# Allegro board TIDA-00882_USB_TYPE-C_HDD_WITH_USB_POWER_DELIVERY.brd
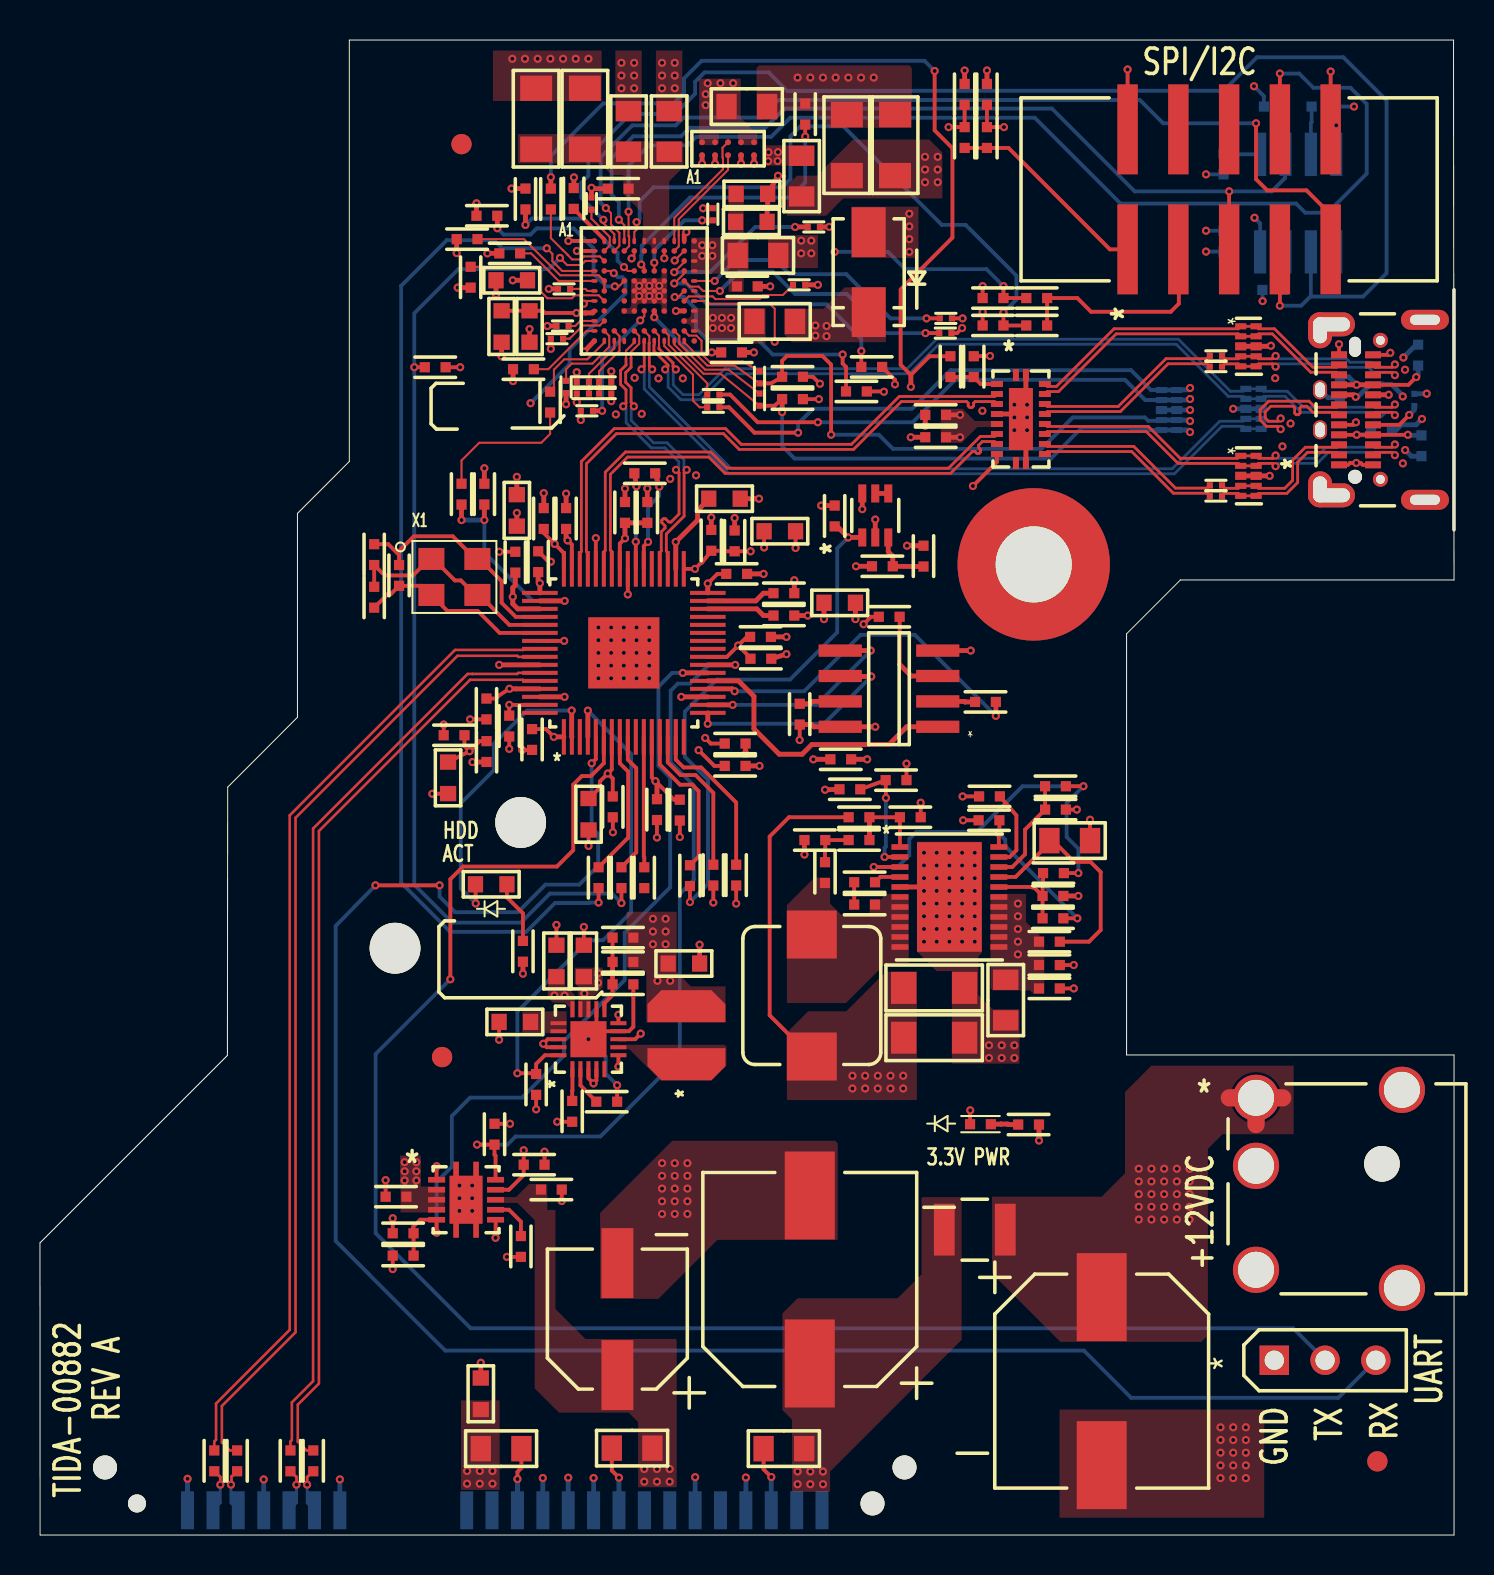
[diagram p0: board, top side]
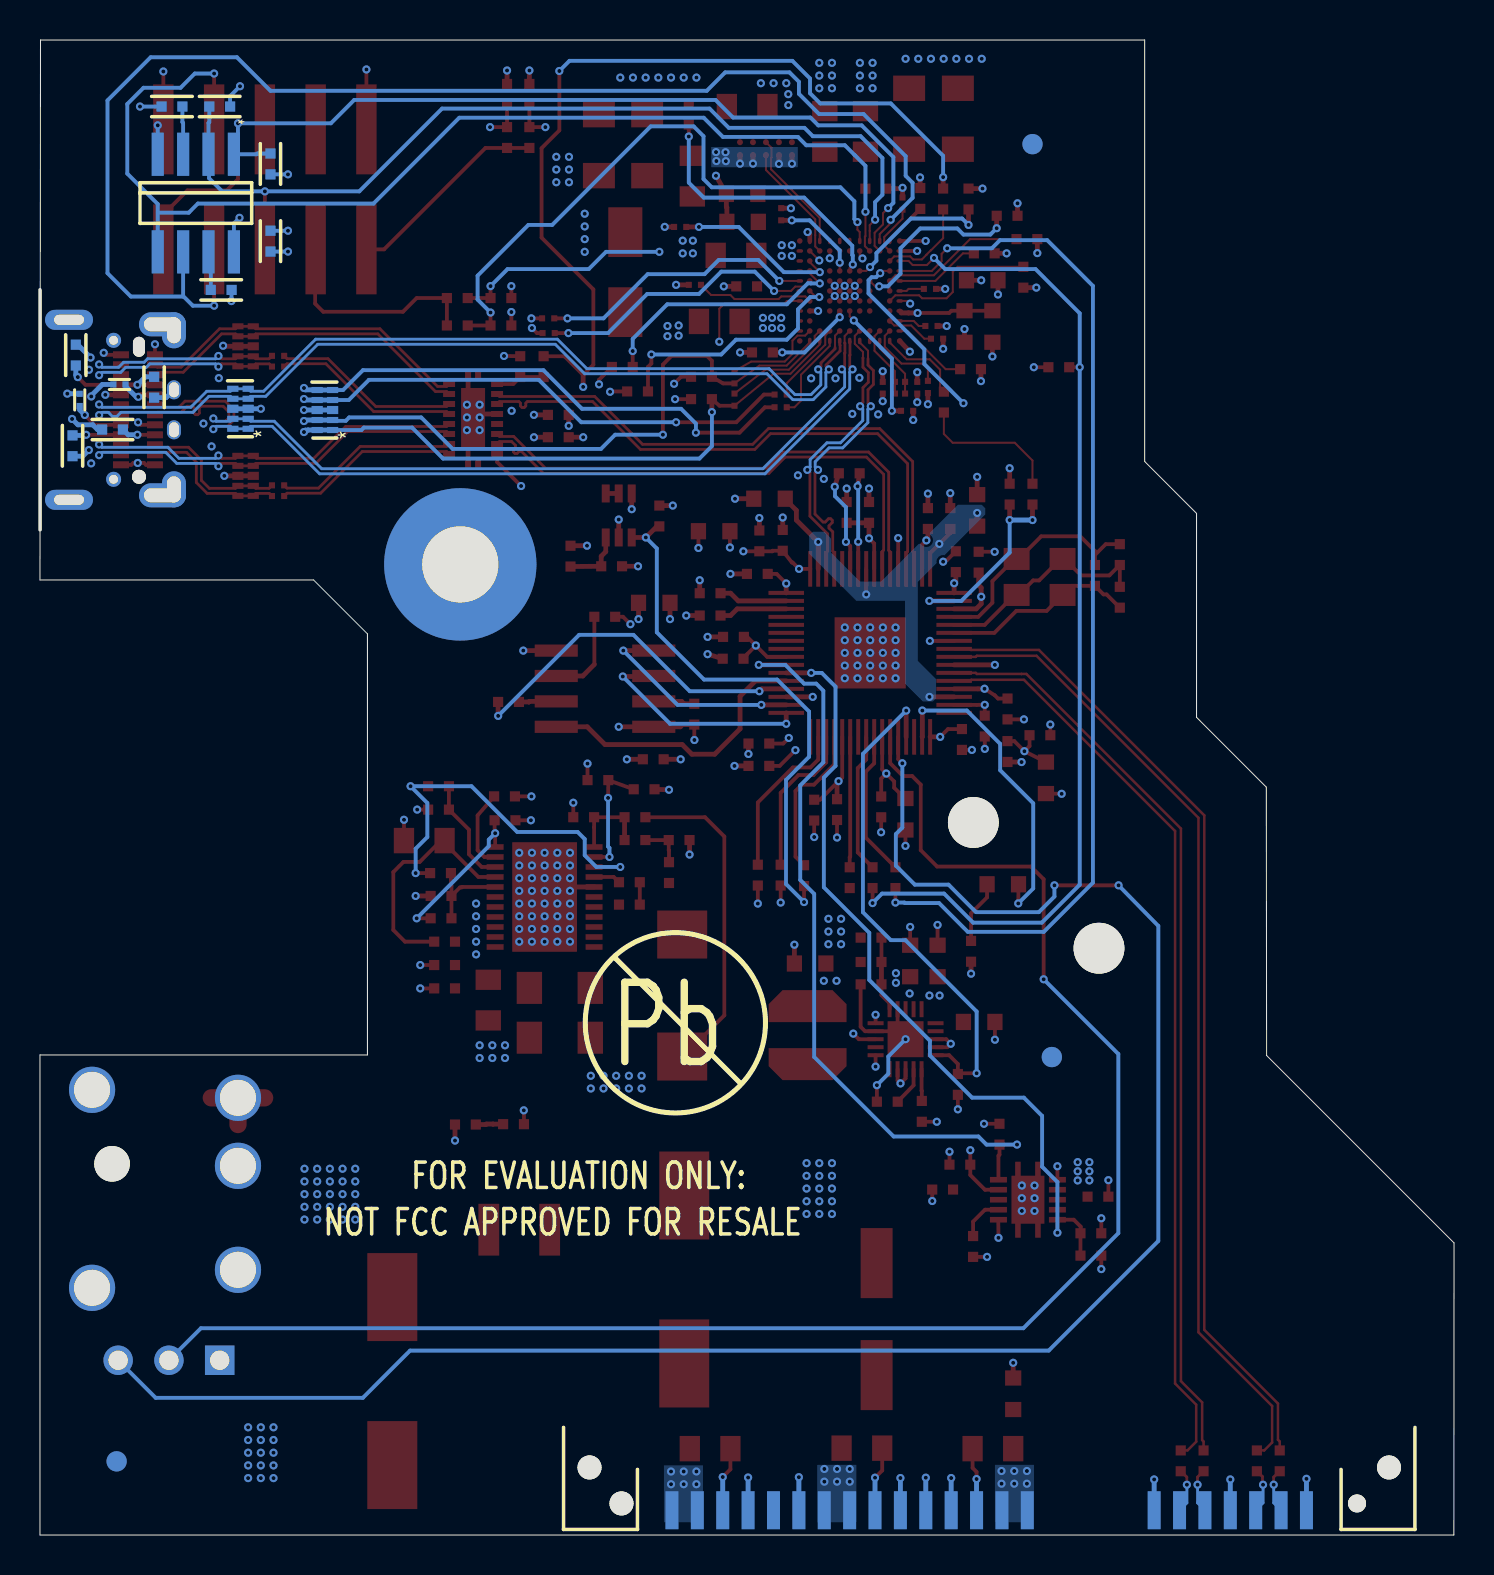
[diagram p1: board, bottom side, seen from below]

Outline 70.75 x 74.75 mm; copper layers: TOP, L2_GND, L3_SIG, L4_PWR, L5_GND, BOTTOM. Coordinates in mm from the lower left corner of the outline.
Outline path: 0,14.61 9.38,23.98 9.39,37.4 12.88,40.88 12.88,51.08 15.48,53.68 15.48,74.75 70.72,74.75 70.75,47.75 57.06,47.75 54.36,45.06 54.36,24 70.75,24 70.75,0 0.01,0 0,14.61

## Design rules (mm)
net group DIFFPAIR0: nets CRX2N CRX2P
net group DIFFPAIR1: nets CTX2N CTX2P
net group DIFFPAIR2: nets CTX1N CTX1P
net group DIFFPAIR3: nets CRX1N CRX1P
net group DIFFPAIR4: nets C_USB_BN C_USB_BP
net group DIFFPAIR5: nets C_USB_TN C_USB_TP
net group DIFFPAIR6: nets CTX2N_C CTX2P_C
net group DIFFPAIR7: nets CTX1N_C CTX1P_C
net group DIFFPAIR8: nets USB3_TX0N USB3_TX0P
net group DIFFPAIR9: nets USB3_RX0N USB3_RX0P
net group DIFFPAIR10: nets SATATXM SATATXP
net group DIFFPAIR11: nets SATARXM SATARXP
net group DIFFPAIR12: nets USB_RP_N USB_RP_P
net group DIFFPAIR13: nets CAP_SATATXM CAP_SATATXP
net group DIFFPAIR14: nets CAP_SATARXM CAP_SATARXP

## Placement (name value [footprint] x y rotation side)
C1  0.01uF  [0402]  68.95 59 270 bottom
C2  0.01uF  [0402]  65.04 57.39 90 bottom
C3  0.01uF  [0402]  69.12 54.46 90 bottom
C4  0.1 uF  [0402]  44.81 54.89 0 top
C5  0.01uF  [0402]  67.12 55.27 180 bottom
C6  0.01 uF  [0402]  44.81 56.01 0 top
C7  0.1uF  [0201]  58.83 58.96 0 top
C8  0.1uF  [0201]  58.83 58.42 0 top
C9  0.1uF  [0201]  58.83 52.48 0 top
C10  0.1uF  [0201]  58.83 51.95 0 top
C11  0.01uF  [0402]  8.72 3.71 90 top
C12  0.01uF  [0402]  12.53 3.71 90 top
C13  0.01uF  [0402]  13.67 3.71 90 top
C14  0.01uF  [0402]  9.86 3.71 90 top
C15  22uF  [0603]  22.06 7.06 90 top
C16  220uF  [CAP_RAD_SM_6P3X5P8MM]  28.89 10.79 180 top
C17  220uF  [CAP_RAD_SM_10X8MM]  38.51 12.78 180 top
C18  0.1uF  [0402]  40.06 38.79 0 top
C19  18pF  [0402]  16.72 46.89 90 top
C20  18pF  [0402]  16.72 49.02 270 top
C21  10uF  [0603]  27.45 36.04 270 top
C22  1uF  [0402]  36.07 43.81 0 top
C23  0.1uF  [0402]  36.05 44.91 0 top
C24  0.1uF  [0402]  28.66 36.41 270 top
C25  0.1uF  [0402]  23.78 48.64 90 top
C26  0.1uF  [0402]  25.2 50.83 90 top
C27  22uF  [0603]  34.25 51.82 0 top
C28  22uF  [0603]  20.42 37.86 270 top
C29  1uF  [0402]  22.34 39.17 270 top
C30  0.1uF  [0402]  23.48 40.45 270 top
C31  0.1uF  [0402]  22.34 41.3 270 top
C32  0.1uF  [0402]  30.87 36.27 270 top
C33  0.01uF  [0402]  24.93 48.67 90 top
C34  0.1uF  [0402]  24.62 39.78 270 top
C35  0.1uF  [0402]  34.78 38.46 0 top
C36  0.1uF  [0402]  32.01 36.25 270 top
C37  0.01uF  [0402]  34.78 39.57 0 top
C38  0.1uF  [0402]  20.72 39.99 180 top
C39  0.1uF  [0402]  34.86 48.06 0 top
C40  1uF  [0402]  26.32 50.83 90 top
C41  0.1uF  [0402]  29.27 51.13 90 top
C42  0.1uF  [0402]  33.59 49.73 90 top
C43  0.1uF  [0402]  34.76 49.71 90 top
C44  0.01uF  [0402]  30.39 51.13 90 top
C45  10uF  [0805]  35.36 71.42 180 top
C46  NC, 22uF  [1206]  40.37 69.49 270 top
C47  NC, 22uF  [1206]  42.78 69.49 270 top
C48  22uF  [1206]  24.82 70.82 270 top
C49  22uF  [1206]  27.26 70.82 270 top
C50  0.1uF  [0402]  28.93 67.32 0 top
C51  0.22uF  [0402]  34.6 59.13 180 top
C52  22uF  [0603]  35.62 67.06 180 top
C53  22uF  [0603]  35.59 65.66 180 top
C54  0.1uF  [0402]  35.39 62.43 180 top
C55  10uF  [0603]  24.49 60.43 90 top
C56  220pF  [0402]  37.65 57.91 180 top
C57  220pF  [0402]  37.65 56.79 180 top
C58  2.2uF  [0402]  26.7 66.83 270 top
C59  10uF  [0603]  23.6 62.74 0 top
C60  2.2uF  [0402]  23.5 64.08 0 top
C61  2.2uF  [0402]  24.19 58.29 0 top
C62  0.01uF  [0402]  59.22 64.69 270 bottom
C63  0.1uF  [0402]  50.5 27.33 0 top
C64  0.1uF  [0402]  50.5 28.5 0 top
C65  10uF  [0805]  48.32 26.75 270 top
C66  0.1uF  [0402]  41.26 31.52 180 top
C67  100uF  [1206]  44.74 27.36 0 top
C68  100uF  [1206]  44.74 24.87 0 top
C69  0.1uF  [0402]  38.77 34.75 180 top
C70  1000pF  [0402]  40.98 34.75 180 top
C71  220uF  [CAP_RAD_SM_10X8MM]  53.12 7.7 0 top
C72  1uF  [0402]  50.68 31.95 0 top
C73  0.1uF  [0402]  17.81 16.92 180 top
C74  22uF  [0603]  32.22 28.57 0 top
C75  30pF  [0402]  29.17 28.65 0 top
C76  22uF  [0603]  25.84 28.7 90 top
C77  22uF  [0603]  27.21 28.7 90 top
C78  0.1uF  [0402]  24.72 18.52 0 top
C79  0.1uF  [0402]  25.59 17.27 0 top
C80  0.1uF  [0402]  28.35 21.67 0 top
C81  22uF  [0603]  23.76 25.65 180 top
C82  4.7uF  [0805]  51.52 34.72 0 top
CN1  10029364-001LF  [CON_SMRT_10029364-001LF]  23.25 3.38 180 bottom
D1  LED White 0603  [0603]  22.58 32.54 0 top
D2  B340A-13-F  [SMA]  41.46 63.14 90 top
D3  LED Green 0402  [LED_0402]  47.05 20.54 180 top
F1  PTC FUSE  [FUSE_SM_135X110X43]  46.77 15.27 0 top
FB1  220 @ 100MHz  [0603]  40.01 46.61 180 top
FB2  220 @ 100MHz  [0603]  23.86 51.23 270 top
FB3  220 @ 100MHz  [0603]  37.02 50.19 180 top
FB4  NC, 21 @ 100MHZ  [0805]  29.45 70.18 90 top
FB5  21 @ 100MHZ  [0805]  31.48 70.18 90 top
FB6  21 @ 100MHZ  [0805]  35.92 63.98 180 top
FB7  21 @ 100MHZ  [0805]  36.76 60.68 0 top
FB8  220 @ 100MHz  [0603]  23.1 60.43 90 top
J1  TypeC_Receptacle_DualSMT_TOP  [USB_TYPEC_UT1211]  65.79 56.26 90 top
J2  NOPOP  [HDR_THVT_1X3_100]  61.76 8.74 90 top
J3  Header 5x2 0.1" Shroud SMT  [HDR_SMVT_SHRD_2X5_100]  59.49 67.28 90 top
J4  2.1mm x 5.5mm  [JACK_THRT_PJ-051AH]  60.84 21.86 0 top
L1  3.3uH  [IND_SM_SRP7030F]  38.62 26.97 270 top
L2  2.2uH  [IND_SM_VLCF4020]  32.34 24.99 90 top
MH1  Mounting Hole  [MFG_150_PTH]  49.72 48.53 0 top
NOREF  -  []  0.01 0 0 top
NOREF#2  -  []  15.76 11.93 90 top
NOREF#3  -  []  70.75 47.75 90 top
NOREF#4  -  []  54.36 24 0 top
NOREF#5  -  [unnamed#2]  21.09 69.55 0 top
NOREF#6  -  [unnamed#2]  24.05 35.63 0 top
NOREF#7  -  []  -3.8 -69.85 0 top
NOREF#8  -  [unnamed#2]  17.76 29.34 0 top
NOREF#9  -  [unnamed#2]  66.91 3.68 0 top
NOREF#10  -  []  0.01 0 0 top
NOREF#11  -  []  70.75 24 90 top
NOREF#12  -  []  70.75 0 90 top
NOREF#13  -  [unnamed#2]  20.12 23.9 0 top
NOREF#14  -  []  70.75 0 90 top
NOREF#15  -  []  15.48 74.75 0 top
NOREF#16  -  []  88.91 38.1 0 top
NOREF#17  -  [unnamed#2]  66.91 3.68 180 bottom
NOREF#18  -  [unnamed#2]  21.09 69.55 180 bottom
NOREF#19  -  [unnamed#2]  20.12 23.9 180 bottom
NOREF#20  -  []  12.39 18.28 180 bottom
NOREF#21  -  []  38.96 25.61 180 bottom
R1  2M  [0201]  68.76 56.76 270 bottom
R2  2M  [0201]  66.77 57.53 180 bottom
R3  0  [0402]  45.55 58.42 270 top
R4  NC, 0  [0402]  46.72 58.42 270 top
R5  10  [0805]  29.62 4.34 180 top
R6  4.7K  [0402]  38.01 41.04 270 top
R7  10  [0805]  23.07 4.32 0 top
R8  4.7K  [0402]  42.49 45.91 180 top
R9  10K  [0402]  30.26 53.09 180 top
R10  10  [0805]  37.22 4.32 180 top
R11  0  [0402]  47.31 41.65 180 top
R12  2M  [0402]  17.97 47.98 90 top
R13  56.2K  [0402]  21.09 52.04 90 top
R14  4.7K  [0402]  37.22 45.97 0 top
R15  4.7K  [0402]  37.22 47.09 0 top
R16  10K  [0402]  22.23 52.04 270 top
R17  330  [0402]  24.16 29.18 90 top
R18  NC, 0  [0402]  30.23 32.87 90 top
R19  0  [0402]  32.52 32.97 90 top
R20  NC, 0  [0402]  33.69 32.99 90 top
R21  0  [0402]  27.95 32.87 90 top
R22  0  [0402]  34.83 32.99 90 top
R23  0  [0402]  29.09 32.87 90 top
R24  NC, 0.005, 1%, 0.25W  [0805]  38.11 67.94 270 top
R25  0  [0402]  25.56 66.8 270 top
R26  0  [0402]  41.61 58.4 180 top
R27  0  [0402]  39.76 50.95 90 top
R28  0  [0201]  36 56.77 90 top
R29  0  [0201]  36 57.89 90 top
R30  NC, 0  [0201]  33.69 56.39 180 top
R31  NC, 0  [0201]  33.69 57.02 180 top
R32  15K  [0402]  21.55 62.89 270 top
R33  1M  [0201]  26.14 60.45 180 top
R34  1M  [0201]  25.87 59.82 180 top
R35  1K  [0402]  24.29 66.8 270 top
R36  1K  [0402]  22.36 65.96 0 top
R37  1M  [0201]  45.32 60.83 0 top
R38  3.3K  [0402]  59.22 68.55 90 bottom
R39  100K  [0402]  40.85 57.18 180 top
R40  3.3K  [0402]  61.76 71.42 0 bottom
R41  3.3K  [0402]  61.68 62.26 0 bottom
R42  3.3K  [0402]  64.14 71.42 0 bottom
R43  3.3K  [0402]  47.38 72.03 270 top
R44  3.3K  [0402]  47.68 61.85 0 top
R45  3.3K  [0402]  46.26 72.03 270 top
R46  3.3K  [0402]  47.68 60.48 0 top
R47  0  [0402]  46.26 69.88 90 top
R48  0  [0402]  49.87 60.48 180 top
R49  NC, 0  [0402]  49.87 61.85 180 top
R50  NC, 0  [0402]  47.38 69.88 90 top
R51  100K  [0402]  21.37 64.8 180 top
R52  100K  [0402]  38.29 71.04 90 top
R54  1M  [0201]  26.32 57.4 270 top
R55  1M  [0201]  27.59 66.57 90 top
R56  NC, 1K  [0201]  27.16 57.66 180 top
R57  NC, 1K  [0201]  28.28 57.66 0 top
R58  1M  [0201]  38.72 65.41 0 top
R59  1M  [0201]  45.3 60.1 0 top
R60  1M  [0201]  37.98 62.51 0 top
R61  1M  [0201]  33.66 66.04 90 top
R62  1M  [0201]  27.16 57.07 180 top
R63  1M  [0201]  28.28 57.07 0 top
R64  NC, 0  [0201]  26.22 62.31 0 top
R65  1M  [0201]  27.36 56.21 180 top
R66  750K  [0402]  44.2 48.95 90 top
R67  470K  [0402]  42.83 37.74 0 top
R68  2K  [0402]  39.28 33.12 90 top
R69  76.8K  [0402]  40.98 35.89 0 top
R70  3.01  [0402]  41.26 32.64 180 top
R71  120K  [0402]  42.15 48.44 0 top
R72  200K  [0402]  40.52 37.29 0 top
R73  NC, TBD  [0402]  50.68 30.84 0 top
R74  NC, TBD  [0402]  50.81 37.44 0 top
R75  100K  [0402]  47.51 36.93 0 top
R76  10K  [0402]  43.54 35.89 0 top
R77  NC, TBD  [0402]  47.48 35.74 0 top
R78  100K  [0402]  50.81 36.27 180 top
R79  100K  [0402]  50.71 33.1 180 top
R80  400K  [0402]  29.17 29.87 180 top
R81  10K  [0402]  22.74 20.04 270 top
R82  475K  [0402]  29.17 27.53 180 top
R83  4.7K  [0402]  18.17 15.09 180 top
R84  4.7K  [0402]  26.63 21.18 90 top
R85  4.7K  [0402]  24.82 22.53 270 top
R86  NC, 4.7K  [0402]  18.17 13.97 180 top
R87  20K  [0402]  24.06 14.43 270 top
R88  330  [0402]  49.46 20.52 0 top
R89  0  [0402]  50.5 29.67 180 top
R90  0  [0402]  25.52 56.65 90 top
R91  10K  [0402]  19.77 58.39 180 top
U1  HD3SS3212  [RKS_R-PVQFN-N20]  49.08 55.8 0 top
U2  TPD4E05U06  [DQA]  60.46 52.96 270 top
U3  TPD4E05U06  [DQA]  60.46 59.44 270 top
U4  TPD4E05U06  [DQA]  56.49 56.25 90 bottom
U5  TPD4E05U06  [DQA]  60.71 56.31 90 bottom
U6  TUSB9261PVP  [PVP_QFP_64]  29.21 44.11 90 top
U7  M25P10-AVMN6TP  [SOIC_8_197X157_50]  42.48 42.32 180 top
U8  NC, CSD87501L  [YJG0010AA]  34.42 69.32 90 top
U9  TPS65982  [ZQZ_BGA_96]  30.23 62.2 0 top
U10  W25Q80DVSNIG  [SOIC_8_197X157_50]  62.95 66.6 270 bottom
U11  TPS53318  [DQP_PSON_22]  45.5 31.9 0 top
U12  TLV3012AIDCK  [DCK_PDSO_6]  41.79 50.98 90 top
U13  TPS650061  [RUK_S_PWQFN-N20]  27.44 24.79 90 top
U14  TPS2561DRC  [DRC_S_PVSON_N10]  21.32 16.76 0 top
X1  40MHz  [ECX-32]  20.73 47.9 0 top

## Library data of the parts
C1-C6 C45-C62 = cc0402
C7-C15 C18-C44 C63-C70 C72-C82 = CAP NP
C16 C17 C71 = CAP POL
CN1 = 0876781001
D1 = DIODE_4
D2 = DIODE SCHOTTKY_1
D3 = DIODE_5
F1 = FUSE
FB1-FB8 = FERRITE BEAD
J1 = USBTypeC_Receptacle_TOPMount_0
J2 = HDR3X1 M .1
J3 = CONN PCB 5x2-S
J4 = BNC_0
L1 = INDUCTOR
L2 = INDUCTOR FERRITE
MH1 = Mounting Hole
R1 R2 R25-R52 R54 R55 R58-R63 R65 R90 R91 = R_2
R3-R23 R56 R57 R64 R66-R89 = R
R24 = RESISTOR
U1 = HD3SS3212_0
U2-U5 = TPD4E05U06
U6 = TUSB9260PAP_0
U7 = Pm25LV512A
U8 = CDS87501L
U9 = TPS65982
U10 = W25Q80SSI
U11 = TPS53318
U12 = TLV3012
U13 = TPS650061_0
U14 = TPS2560DRC_1
X1 = X OR Y_0

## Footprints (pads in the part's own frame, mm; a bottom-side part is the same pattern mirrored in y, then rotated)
0201
  rect 0.305x0.305 smd: 1(-0.305,0) 2(0.305,0)
0402
  rect 0.508x0.508 smd: 1(-0.521,0) 2(0.521,0)
0603
  rect 0.762x0.813 smd: 1(-0.787,0) 2(0.787,0)
0805
  rect 1.016x1.27 smd: 1(-1.016,0) 2(1.016,0)
1206
  rect 1.27x1.6 smd: 1(-1.524,0) 2(1.524,0)
CAP_RAD_SM_6P3X5P8MM
  rect 1.6x3.5 smd: 1(0,2.8) 2(0,-2.8)
CAP_RAD_SM_10X8MM
  rect 2.5x4.4 smd: 1(0,4.2) 2(0,-4.2)
CON_SMRT_10029364-001LF
  round 1.2 hole 1.2 unplated: (-20,0) (-18.4,-1.8) (20,0)
  round 0.9 hole 0.9 unplated: (18.4,-1.8)
  rect 0.65x1.9 smd: P1(1.905,-2.14) P2(0.635,-2.14) P3(-0.635,-2.14) P4(-1.905,-2.14) P5(-3.175,-2.14) P6(-4.445,-2.14) P7(-5.715,-2.14) P8(-6.985,-2.14) P9(-8.255,-2.14) P10(-9.525,-2.14) P11(-10.795,-2.14) P12(-12.065,-2.14) P13(-13.335,-2.14) P14(-14.605,-2.14) P15(-15.875,-2.14) S1(15.87,-2.14) S2(14.6,-2.14) S3(13.33,-2.14) S4(12.06,-2.14) S5(10.79,-2.14) S6(9.52,-2.14) S7(8.25,-2.14)
DCK_PDSO_6
  rect 0.9x0.4 smd: 1(-1.1,0.65) 2(-1.1,0) 3(-1.1,-0.65) 4(1.1,-0.65) 5(1.1,0) 6(1.1,0.65)
DQA
  rect 0.305x0.559 smd: 1(-1,-0.385) 2(-0.5,-0.385) 4(0.5,-0.385) 5(1,-0.385) 6(1,0.385) 7(0.5,0.385) 9(-0.5,0.385) 10(-1,0.385)
  rect 0.406x0.559 smd: 3(0,-0.385) 8(0,0.385)
DQP_PSON_22
  rect 0.85x0.28 smd: 1(-2.475,2.5) 2(-2.475,2) 3(-2.475,1.5) 4(-2.475,1) 5(-2.475,0.5) 6(-2.475,0) 7(-2.475,-0.5) 8(-2.475,-1) 9(-2.475,-1.5) 10(-2.475,-2) 11(-2.475,-2.5) 12(2.475,-2.5) 13(2.475,-2) 14(2.475,-1.5) 15(2.475,-1) 16(2.475,-0.5) 17(2.475,0) 18(2.475,0.5) 19(2.475,1) 20(2.475,1.5) 21(2.475,2) 22(2.475,2.5)
  rect 3.24x5.48 smd: 23(0,0)
DRC_S_PVSON_N10
  rect 0.85x0.28 smd: 1(-1.475,1) 2(-1.475,0.5) 3(-1.475,0) 4(-1.475,-0.5) 5(-1.475,-1) 6(1.475,-1) 7(1.475,-0.5) 8(1.475,0) 9(1.475,0.5) 10(1.475,1)
  custom 0.412x0.412 smd: 11(0,0)
ECX-32
  rect 1.3x1.1 smd: 1(-1.15,-0.9) 2(1.15,-0.9) 3(1.15,0.9) 4(-1.15,0.9)
FUSE_SM_135X110X43
  rect 1.041x2.591 smd: 1(-1.524,0) 2(1.524,0)
HDR_SMVT_SHRD_2X5_100
  rect 4.5x1.02 smd: 1(-3,5.08) 2(3,5.08) 3(-3,2.54) 4(3,2.54) 5(-3,0) 6(3,0) 7(-3,-2.54) 8(3,-2.54) 9(-3,-5.08) 10(3,-5.08)
HDR_THVT_1X3_100
  rect 1.473x1.473 hole 0.965: 1(0,0)
  round 1.473 hole 0.965: 2(0,-2.54) 3(0,-5.08)
IND_SM_SRP7030F
  rect 2.4x2.5 smd: 1(-3.05,0) 2(3.05,0)
IND_SM_VLCF4020
  custom 0.4x0.4 smd: 1(-1.45,0) 2(1.45,0)
JACK_THRT_PJ-051AH
  round 1.778 hole 1.778 unplated: (6.3,-3.3)
  round 2.311 hole 1.803: 1(0,0) 2(0,-8.6) 3(0,-3.4) 4(7.3,-9.5) 5(7.3,0.4)
LED_0402
  rect 0.508x0.508 smd: 1(-0.521,0) 2(0.521,0)
MFG_150_PTH
  round 7.62 hole 3.81: 1(0,0)
PVP_QFP_64
  rect 1.78x0.2 smd: 1(-4.2,3) 2(-4.2,2.6) 3(-4.2,2.2) 4(-4.2,1.8) 5(-4.2,1.4) 6(-4.2,1) 7(-4.2,0.6) 8(-4.2,0.2) 9(-4.2,-0.2) 10(-4.2,-0.6) 11(-4.2,-1) 12(-4.2,-1.4) 13(-4.2,-1.8) 14(-4.2,-2.2) 15(-4.2,-2.6) 16(-4.2,-3) 33(4.2,-3) 34(4.2,-2.6) 35(4.2,-2.2) 36(4.2,-1.8) 37(4.2,-1.4) 38(4.2,-1) 39(4.2,-0.6) 40(4.2,-0.2) 41(4.2,0.2) 42(4.2,0.6) 43(4.2,1) 44(4.2,1.4) 45(4.2,1.8) 46(4.2,2.2) 47(4.2,2.6) 48(4.2,3)
  rect 0.2x1.78 smd: 17(-3,-4.2) 18(-2.6,-4.2) 19(-2.2,-4.2) 20(-1.8,-4.2) 21(-1.4,-4.2) 22(-1,-4.2) 23(-0.6,-4.2) 24(-0.2,-4.2) 25(0.2,-4.2) 26(0.6,-4.2) 27(1,-4.2) 28(1.4,-4.2) 29(1.8,-4.2) 30(2.2,-4.2) 31(2.6,-4.2) 32(3,-4.2) 49(3,4.2) 50(2.6,4.2) 51(2.2,4.2) 52(1.8,4.2) 53(1.4,4.2) 54(1,4.2) 55(0.6,4.2) 56(0.2,4.2) 57(-0.2,4.2) 58(-0.6,4.2) 59(-1,4.2) 60(-1.4,4.2) 61(-1.8,4.2) 62(-2.2,4.2) 63(-2.6,4.2) 64(-3,4.2)
  rect 3.56x3.56 smd: 65(0,0)
RKS_R-PVQFN-N20
  rect 0.3x0.6 smd: 1(-0.25,2.2) 10(-0.25,-2.2) 11(0.25,-2.2) 20(0.25,2.2)
  rect 0.6x0.3 smd: 2(-1.2,1.75) 3(-1.2,1.25) 4(-1.2,0.75) 5(-1.2,0.25) 6(-1.2,-0.25) 7(-1.2,-0.75) 8(-1.2,-1.25) 9(-1.2,-1.75) 12(1.2,-1.75) 13(1.2,-1.25) 14(1.2,-0.75) 15(1.2,-0.25) 16(1.2,0.25) 17(1.2,0.75) 18(1.2,1.25) 19(1.2,1.75)
  rect 1.2x3.1 smd: 21(0,0)
RUK_S_PWQFN-N20
  rect 0.8x0.2 smd: 1(-1.5,0.8) 2(-1.5,0.4) 3(-1.5,0) 4(-1.5,-0.4) 5(-1.5,-0.8) 11(1.5,-0.8) 12(1.5,-0.4) 13(1.5,0) 14(1.5,0.4) 15(1.5,0.8)
  rect 0.2x0.8 smd: 6(-0.8,-1.5) 7(-0.4,-1.5) 8(0,-1.5) 9(0.4,-1.5) 10(0.8,-1.5) 16(0.8,1.5) 17(0.4,1.5) 18(0,1.5) 19(-0.4,1.5) 20(-0.8,1.5)
  rect 1.8x1.8 smd: 21(0,0)
SMA
  rect 2.489x1.702 smd: 1(-2,0) 2(2,0)
SOIC_8_197X157_50
  rect 2.159x0.61 smd: 1(-2.44,1.905) 2(-2.44,0.635) 3(-2.44,-0.635) 4(-2.44,-1.905) 5(2.44,-1.905) 6(2.44,-0.635) 7(2.44,0.635) 8(2.44,1.905)
unnamed#2
  round 1.016 smd: (0,0)
USB_TYPEC_UT1211
  round 0.7 hole 0.7 unplated: (-3.35,0)
  oval 1x0.6 hole 1x0.6 unplated: (3.15,0)
  round 0.75 hole 0.45: 1(-3.475,-1.27) 2(3.475,-1.27)
  oval 1x2.4 hole 0.5x1.5: 3(-4.5,-3.5) 4(4.5,-3.5)
  oval 0.95x0.7 hole 0.75x0.5: 5(-1,1.75) 6(1,1.75)
  oval 1.2x2.35 hole 0.7x1.85: 7(4.275,1.175) 8(-4.275,1.175)
  oval 1.8x1.2 hole 1.3x0.7: 9(-3.975,1.75) 10(3.975,1.75)
  rect 0.35x0.8 smd: A1(-2.75,0.8) A2(-2.25,0.8) A3(-1.75,0.8) A4(-1.25,0.8) A5(-0.75,0.8) A6(-0.25,0.8) A7(0.25,0.8) A8(0.75,0.8) A9(1.25,0.8) A10(1.75,0.8) A11(2.25,0.8) A12(2.75,0.8) B1(2.75,-0.9) B2(2.25,-0.9) B3(1.75,-0.9) B4(1.25,-0.9) B5(0.75,-0.9) B6(0.25,-0.9) B7(-0.25,-0.9) B8(-0.75,-0.9) B9(-1.25,-0.9) B10(-1.75,-0.9) B11(-2.25,-0.9) B12(-2.75,-0.9)
YJG0010AA
  round 0.3 smd: A1(-0.325,1.3) A2(0.325,1.3) B1(-0.325,0.65) B2(0.325,0.65) C1(-0.325,0) C2(0.325,0) D1(-0.325,-0.65) D2(0.325,-0.65) E1(-0.325,-1.3) E2(0.325,-1.3)
ZQZ_BGA_96
  round 0.28 smd: A1(-2.5,2.5) A11(2.5,2.5) B2(-2,2) B3(-1.5,2) B4(-1,2) B5(-0.5,2) B6(0,2) B7(0.5,2) B8(1,2) B9(1.5,2) B10(2,2) C2(-2,1.5) C10(2,1.5) D2(-2,1) D5(-0.5,1) D6(0,1) D7(0.5,1) D8(1,1) D10(2,1) E2(-2,0.5) E4(-1,0.5) E5(-0.5,0.5) E6(0,0.5) E7(0.5,0.5) E8(1,0.5) E10(2,0.5) F2(-2,0) F4(-1,0) F5(-0.5,0) F6(0,0) F7(0.5,0) F8(1,0) F10(2,0) G2(-2,-0.5) G4(-1,-0.5) G5(-0.5,-0.5) G6(0,-0.5) G7(0.5,-0.5) G8(1,-0.5) G10(2,-0.5) H2(-2,-1) H4(-1,-1) H5(-0.5,-1) H6(0,-1) H7(0.5,-1) H8(1,-1) H10(2,-1) J2(-2,-1.5) J10(2,-1.5) K2(-2,-2) K3(-1.5,-2) K4(-1,-2) K5(-0.5,-2) K6(0,-2) K7(0.5,-2) K8(1,-2) K9(1.5,-2) K10(2,-2) L1(-2.5,-2.5) L11(2.5,-2.5)
  oval 0.18x0.33 smd: A2(-2,2.5) A3(-1.5,2.5) A4(-1,2.5) A5(-0.5,2.5) A6(0,2.5) A7(0.5,2.5) A8(1,2.5) A9(1.5,2.5) A10(2,2.5) L2(-2,-2.5) L3(-1.5,-2.5) L4(-1,-2.5) L5(-0.5,-2.5) L6(0,-2.5) L7(0.5,-2.5) L8(1,-2.5) L9(1.5,-2.5) L10(2,-2.5)
  oval 0.33x0.18 smd: B1(-2.5,2) B11(2.5,2) C1(-2.5,1.5) C11(2.5,1.5) D1(-2.5,1) D11(2.5,1) E1(-2.5,0.5) E11(2.5,0.5) F1(-2.5,0) F11(2.5,0) G1(-2.5,-0.5) G11(2.5,-0.5) H1(-2.5,-1) H11(2.5,-1) J1(-2.5,-1.5) J11(2.5,-1.5) K1(-2.5,-2) K11(2.5,-2)

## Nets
GND: C1.1 C2.1 C3.1 C4.1 C5.1 C6.1 C15.2 C16.2 C17.2 C18.2 C21.2 C22.2 C23.2 C24.2 C25.2 C26.2 C27.2 C28.2 C29.2 C30.2 C31.2 C32.2 C33.2 C34.2 C35.2 C36.2 C37.2 C38.2 C39.2 C40.2 C41.2 C42.2 C43.2 C44.2 C45.1 C46.1 C47.1 C48.1 C49.1 C50.1 C51.1 C52.1 C53.1 C54.1 C55.1 C56.1 C57.1 C58.1 C59.1 C60.1 C61.1 C62.1 C63.2 C64.2 C65.2 C67.2 C68.2 C71.2 C72.2 C73.2 C74.2 C76.2 C77.2 C78.2 C79.2 C80.2 C81.2 C82.2 CN1.P4(GND#P4) CN1.P5(GND#P5) CN1.P6(GND#P6) CN1.P10(GND#P10) CN1.P12(GND#P12) CN1.S1(GND#S1) CN1.S4(GND#S4) CN1.S7(GND#S7) D2.2(ANODE) J1.1(SHIELD1) J1.2(SHIELD2) J1.3(SHIELD3) J1.4(SHIELD4) J1.5(SHIELD5) J1.6(SHIELD6) J1.7(SHIELD7) J1.8(SHIELD8) J1.9(SHIELD9) J1.10(SHIELD10) J1.A1(GND0) J1.A12(GND1) J1.B1(GND2) J1.B12(GND3) J2.1 J3.2(6) J3.10 J4.2(S) J4.3(SW) J4.4(GND#4) J4.5(GND#5) MH1.1(GND) R1.1 R2.1 R4.1 R16.1 R32.2 R33.2 R34.2 R37.2 R51.2 R52.2 R54.2 R55.2 R58.2 R59.2 R60.2 R61.2 R62.2 R63.2 R64.1 R65.2 R71.1 R72.1 R75.1 R76.2 R77.1 R78.1 R82.1 R86.2 R87.2 R88.2 U1.5(GND#5) U1.11(GND#11) U1.20(GND#20) U1.21(PPAD) U2.3(GND#3) U2.8(GND#8) U3.3(GND#3) U3.8(GND#8) U4.3(GND#3) U4.8(GND#8) U5.3(GND#3) U5.8(GND#8) U6.44(VSS#44) U6.58(VSS#58) U6.65(VSS#65) U7.4(GND) U9.A1(GND#A1) U9.B8(GND#B8) U9.D8(GND#D8) U9.E5(GND#E5) U9.E6(GND#E6) U9.E7(GND#E7) U9.E8(GND#E8) U9.F5(GND#F5) U9.F6(GND#F6) U9.F7(GND#F7) U9.F8(GND#F8) U9.G5(GND#G5) U9.G6(GND#G6) U9.G7(GND#G7) U9.G8(GND#G8) U9.H4(GND#H4) U9.H5(GND#H5) U9.H8(GND#H8) U9.L1(GND#L1) U10.4(GND) U11.5(ROVP) U11.23(GND) U12.2(V-) U13.6(PGND) U13.9(MODE) U13.12(AGND) U13.21(PWR_PAD) U14.1(GND) U14.11(PAD)
SV5: CN1.P7(V5#P7) R5.2
SV12: CN1.P13(V12#P13) R10.2
SV33: CN1.P3(V33#P3) R7.2
VDD_1P1V: C28.1 C29.1 C30.1 C31.1 C32.1 C33.1 C34.1 C35.1 C36.1 C37.1 C38.1 C39.1 C40.1 C41.1 C42.1 C43.1 C44.1 FB3.2 U6.1(VDD#1) U6.12(VDD#12) U6.19(VDD#19) U6.32(VDD#32) U6.33(VDD#33) U6.41(VDD#41) U6.47(VDD#47) U6.49(VDD#49) U6.55(VDD#55) U6.61(VDD#61) U6.63(VDD#63)
VDD_3P3V: C21.1 C22.1 C23.1 C24.1 C25.1 FB1.2 R14.2 R15.2 R81.1 R83.2 R85.2 U6.7(VDDSHV#7) U6.24(VDDSHV#24) U6.51(VDD33)
VDDA_3P3V: C26.1 C27.1 FB2.2 U6.34(VDDA33#34) U6.40(VDDA33#40) U6.48(VDDA33#48) U6.62(VDDA33#62)
VIN_3V3: C55.2 FB8.2 U9.B1(VDDIO) U9.H1(VIN_3V3)
VSSOSC: C19.2 C20.2 U6.53(VSSOSC) X1.2(GND#2) X1.4(GND#4)
3212OEN: R3.2 R4.2 U1.2(OEN)
53318_EN: R67.1 R72.2 U11.2(EN)
53318_LL: C66.1 L1.1 R68.1 U11.6(LL1) U11.7(LL2) U11.8(LL3) U11.9(LL4) U11.10(LL5) U11.11(LL6)
53318_MODE: R74.1 R78.2 U11.20(MODE)
65982_5V: C52.2 C53.2 C54.2 FB6.2 U9.A11(PP_5V0_2) U9.B11(PP_5V0_1) U9.C11(PP_5V0_3) U9.D11(PP_5V0_4) U9.H10(PP_CABLE)
65982_VBUS: C45.2 FB7.1 U8.A2(S2_1) U8.B2(S2_2) U8.D2(S2_3) U8.E2(S2_4) U9.H11(VBUS1) U9.J10(VBUS2) U9.J11(VBUS3) U9.K11(VBUS4)
87501_S1: R24.1 U8.A1(S1_1) U8.B1(S1_2) U8.D1(S1_3) U8.E1(S1_4) U9.A10(SENSEN)
AUX_N: R34.1 U9.J2(AUX_N)
AUX_P: R33.1 U9.J1(AUX_P)
BOARD_1P1V: C74.1 C75.2 FB3.1 L2.2 R80.1
BOARD_1P8V: C81.1 U13.16(FB_LDO2) U13.17(VLDO2)
BOARD_3P3V: C4.2 C6.2 C15.1 C18.1 C77.1 CN1.P1(V33#P1) CN1.P2(V33#P2) D3.2(A) FB1.1 FB2.1 FB8.1 R6.2 R7.1 R8.2 R17.1 U1.6(VCC) U7.8(VCC) U13.13(FB_LDO1) U13.14(VLDO1)
BOARD_5V: C67.1 C68.1 C69.2 C73.1 FB4.2 FB6.1 L1.2 R69.1 U14.2(IN#2) U14.3(IN#3) U14.4(EN1)
BOARD_12V: C46.2 C47.2 C63.1 C64.1 C65.1 C71.1 F1.2 FB5.2 J4.1(T) R24.2 R66.2 R67.2 R89.2 U9.B10(SENSEP) U11.12(VIN1) U11.13(VIN2) U11.14(VIN3) U11.15(VIN4) U11.16(VIN5) U11.17(VIN6)
C_CC1: C57.2 J1.A5(CC1) R28.1 U4.1(D1+) U4.10(NC10) U9.L9(C_CC1)
C_CC2: C56.2 J1.B5(CC2) R29.1 U4.2(D1-) U4.9(NC9) U9.L10(C_CC2)
C_USB_BN: J1.B7(DN2) U5.4(D2+) U5.7(NC7) U9.L7(C_USB_BN)
C_USB_BP: J1.B6(DP2) U5.5(D2-) U5.6(NC6) U9.K7(C_USB_BP)
C_USB_TN: J1.A7(DN1) U5.1(D1+) U5.10(NC10) U9.L6(C_USB_TN)
C_USB_TP: J1.A6(DP1) U5.2(D1-) U5.9(NC9) U9.K6(C_USB_TP)
CABLE_PLUG: R13.2 R90.1
CAP_SATARXM: C12.1 CN1.S5(B-)
CAP_SATARXP: C13.1 CN1.S6(B+)
CAP_SATATXM: C11.1 CN1.S2(A+)
CAP_SATATXP: C14.1 CN1.S3(A-)
CRX1N: J1.B10(SSRXN1) U1.15(C0P) U2.1(D1+) U2.10(NC10)
CRX1P: J1.B11(SSRXP1) U1.14(C0N) U2.2(D1-) U2.9(NC9)
CRX2N: J1.A10(SSRXN2) U1.18(B0N) U3.2(D1-) U3.9(NC9)
CRX2P: J1.A11(SSRXP2) U1.19(B0P) U3.1(D1+) U3.10(NC10)
CSBU1: J1.A8(SBU1) R2.2 R31.1 U4.4(D2+) U4.7(NC7)
CSBU1_TPS65982: R31.2 U9.K8(C_SBU1)
CSBU2: J1.B8(SBU2) R1.2 R30.1 U4.5(D2-) U4.6(NC6)
CSBU2_TPS65982: R30.2 U9.L8(C_SBU2)
CTX1N: C9.2 J1.A3(SSTXN1) U2.4(D2+) U2.7(NC7)
CTX1N_C: C9.1 U1.13(C1P)
CTX1P: C10.2 J1.A2(SSTXP1) U2.5(D2-) U2.6(NC6)
CTX1P_C: C10.1 U1.12(C1N)
CTX2N: C8.2 J1.B3(SSTXN2) U3.5(D2-) U3.6(NC6)
CTX2N_C: C8.1 U1.16(B1N)
CTX2P: C7.2 J1.B2(SSTXP2) U3.4(D2+) U3.7(NC7)
CTX2P_C: C7.1 U1.17(B1P)
DBG_CTL1: R36.2 U9.E4(DBG_CTL1)
DBG_CTL2: R35.2 U9.D5(DBG_CTL2)
DEBUG1: R90.2 U9.L2(DEBUG1)
DEBUG2: R54.1 U9.K2(DEBUG2)
DEBUG3: R56.1 R62.1 U9.L3(DEBUG3)
DEBUG4: R57.1 R63.1 U9.K3(DEBUG4)
FAULT#: R81.2 U6.23(SPI_CS2_GPIO11) U14.6(FAULT2Z) U14.10(FAULT1Z)
FB_DCDC: C75.1 R80.2 R82.2 U13.11(FB_DCDC)
FREQSEL0: R14.1 U6.30(FREQSEL0)
FREQSEL1: R15.1 U6.31(FREQSEL1)
FUSE_12V: C17.1 CN1.P14(V12#P14) CN1.P15(V12#P15) F1.1 R10.1
G1: R28.2 U9.K9(RPD_G1)
G2: R29.2 U9.K10(RPD_G2)
GPIO0: R55.1 U9.B2(GPIO0)
GPIO0_9261: R21.2 U6.8(GPIO0)
GPIO1: R25.2 U9.C2(GPIO1)
GPIO1_9261: R23.2 U6.9(GPIO1)
GPIO2: R26.2 U9.D10(GPIO2)
GPIO3: R27.2 U9.G11(GPIO3)
GPIO3_9261: R18.2 U6.11(GPIO3)
GPIO4: R58.1 U9.C10(GPIO4)
GPIO4_9261: R19.2 U6.13(GPIO4)
GPIO5: R59.1 U9.E10(GPIO5)
GPIO5_9261: R20.2 U6.14(GPIO5)
GPIO6: R60.1 U9.G10(GPIO6)
GPIO6_9261: R22.2 U6.15(GPIO6)
GPIO7: R61.1 U9.D7(GPIO7)
GPIO8: R65.1 U9.H6(GPIO8)
GRST#: R85.1 U6.4(GRSTZ) U13.20(RST#)
HDD_LED#: D1.1(K) U6.2(PWM0)
HLD#: R6.1 U7.7(HOLD#)
HRESET: R52.1 U9.D6(HRESET)
HV_GATE1: U8.C1(G1) U9.B9(HV_GATE1)
HV_GATE2: U8.C2(G2) U9.A9(HV_GATE2)
I2C_ADDR: R64.2 U9.F1(I2C_ADDR)
I2C_IRQ1Z: R23.1 R91.2 U9.C1(I2C_IRQ1Z)
I2C_SCL: J3.1 R47.1 R50.1
I2C_SCL1: R22.1 R43.2 R50.2 U9.D2(I2C_SCL1)
I2C_SCL2: R45.2 R47.2 U9.B5(I2C_SCL2)
I2C_SDA: J3.3(2) R48.1 R49.1
I2C_SDA1: R21.1 R44.2 R49.2 U9.D1(I2C_SDA1)
I2C_SDA2: R46.2 R48.2 U9.A5(I2C_SDA2)
ILIM1: R87.1 U14.7(ILIM)
JACK_DETECT: R19.1 R27.1 U12.1(OUT)
LDO_1V8A: C61.2 U9.K1(LDO_1V8A)
LDO_1V8D: C58.2 U9.A2(LDO_1V8D)
LDO_3V3: C59.2 C62.2 R35.1 R36.1 R38.1 R39.1 R40.1 R41.1 R42.2 R43.1 R44.1 R45.1 R46.1 R56.2 R57.2 R91.1 U9.G1(LDO_3V3) U10.8(VCC) U12.6(V+)
LDO_BMC: C60.2 U9.E1(LDO_BMC)
MR#: R84.2 U13.1(MR#)
PD_BUSPWRZ: R39.2 U9.F10(BUSPOWERZ)
PD_MRESET: R37.1 U9.E11(MRESET)
PGOOD: R74.2 R79.1 U11.3(PGOOD)
PMIC_5V: C76.1 C78.1 R84.1 U13.3(EN_LDO1) U13.4(EN_LDO2) U13.8(VINDCDC) U13.10(EN_DCDC) U13.15(VINLDO1) U13.18(VINLDO2) U13.19(RSTSNS) U14.9(OUT1)
POL: R26.1 U1.9(SEL)
PP_HV: C48.2 C49.2 C50.2 FB4.1 FB5.1 U9.A6(PP_HV1) U9.A7(PP_HV2) U9.A8(PP_HV3) U9.B7(PP_HV4)
R_OSC: R32.1 U9.G2(R_OSC)
REF1: U12.4(IN-) U12.5(REF)
REMOTE_WAKE: R18.1
RF: R73.2 R77.2 U11.22(RF)
SATA_5V: C16.1 C79.1 CN1.P8(V5#P8) CN1.P9(V5#P9) R5.1 U14.8(OUT2)
SATA_EN: R83.1 R86.1 U6.22(SPI_CS1_GPIO10) U14.5(EN2)
SATARXM: C12.2 U6.59(SATA_RXM)
SATARXP: C13.2 U6.60(SATA_RXP)
SATATXM: C11.2 U6.56(SATA_TXM)
SATATXP: C14.2 U6.57(SATA_TXP)
SPI_CE#: U6.21(SPI_CS0) U7.1(CE#)
SPI_CLK: J3.7(4) U9.A3(SPI_CLK) U10.6(CLK)
SPI_HOLD#: R41.2 U10.7(/HOLD)
SPI_MISO: J3.5(3) R40.2 U9.A4(SPI_MISO) U10.2(DO)
SPI_MOSI: J3.8(9) U9.B4(SPI_MOSI) U10.5(DI)
SPI_SCK: U6.17(SPI_SCLK) U7.6(SCK)
SPI_SI: U6.18(SPI_DATA_OUT) U7.5(SI)
SPI_SO: R11.1 U6.20(SPI_DATA_IN)
SPI_SO_J: R11.2 U7.2(SO)
SPI_SSZ: J3.9(5) R38.2 U9.B3(SPI_SSZ) U10.1(/CS)
SPI_WP#: R42.1 U10.3(/WP)
SS: C51.2 U9.H7(SS)
SS_MUX_EN#: R3.1 R20.1 R25.1
SW_1P1V: L2.1 U13.7(SW)
TLV_INP: R66.1 R71.2 U12.3(IN+)
TRIP: R75.2 U11.21(TRIP)
TRST: C80.1 U13.2(TRST)
TYPEC_VBUS: C1.2 C2.2 C3.2 C5.2 D2.1(CATHODE) FB7.2 J1.A4(VBUS1) J1.A9(VBUS2) J1.B4(VBUS3) J1.B9(VBUS4)
UART_RX: J2.3 U6.5(UART_RX_GPIO8)
UART_TX: J2.2 U6.6(UART_TX_GPIO9)
UART_TX_RX: R51.1 U9.E2(UART_TX) U9.F2(UART_RX)
USB3_RX0N: U1.4(A0N) U6.45(USB_SSRXM)
USB3_RX0P: U1.3(A0P) U6.46(USB_SSRXP)
USB3_TX0N: U1.8(A1N) U6.42(USB_SSTXM)
USB3_TX0P: U1.7(A1P) U6.43(USB_SSTXP)
USB_R1: R9.1 U6.38(USB_R1)
USB_R1RTN: R9.2 U6.39(USB_R1RTN)
USB_RP_N: U6.35(USB_DM) U9.K5(USB_RP_N)
USB_RP_P: U6.36(USB_DP) U9.L5(USB_RP_P)
USB_VBUS: R13.1 R16.2 U6.50(USB_VBUS)
VBST: R70.1 U11.4(VBST)
VFB: C70.1 R69.2 R76.1 U11.1(VFB)
VFB_C: C69.1 C70.2 R68.2
VREG: C72.1 R73.1 R79.2 U11.18(VREG)
WP#: R8.1 U7.3(WP#)
XI: C20.1 R12.2 U6.52(XI) X1.3(XI)
XO: C19.1 R12.1 U6.54(XO) X1.1(XO)
N17726709: D1.2(A) R17.2
N17832078: C82.1 R89.1 U11.19(VDD)
N17839350: C66.2 R70.2
N17883338: D3.1(K) R88.1

Pads without a net: CN1 P11; J3 4 6; U1 1 10; U6 3 10 16 25 26 27 28 29 37 64; U9 B6 F4 F11 G4 H2 K4 L4 L11; U13 5

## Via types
v1: diameter 0.406, hole 0.203, TOP to BOTTOM, 592 vias

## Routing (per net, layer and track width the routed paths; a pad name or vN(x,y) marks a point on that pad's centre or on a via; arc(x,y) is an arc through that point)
GND: length 251.8
  TOP w0.102: U9.B8 v1(31.23,63.84)
  TOP w0.191: R4.1 v1(47.53,58.95) ; U13.12 27.84,25.19 ; 27.84,25.19 U13.9 29.47,25.19 29.69,25.41 R82.1 ; 27.84,25.19 v1(27.44,24.79) ; C38.2 v1(20.2,40.53) ; C25.2 v1(22.98,49.16) ; C36.2 v1(32.01,34.9) ; U14.1 v1(19.84,18.44) ; v1(39.02,57.56) 38.67,57.91 C56.1 ; R37.2 v1(46.16,60.83) ; J1.B12 66.17,53.51 66.08,53.6 v1(65.86,53.6) 65.54,53.6 65.45,53.51 J1.A1 ; v1(25.56,48.67) 25.47,48.76 25.35,48.76 C33.2 ; R59.2 45.88,60.1 v1(46.13,60.35) ; U6.44 v1(27.81,49.85) ; v1(67.56,59.11) 67.46,59.01 J1.B1 ; C80.2 v1(28.87,22.49) ; R75.1 v1(46.16,36.93) ; C30.2 v1(23.48,39.31) ; C63.2 v1(51.72,27.33) ; J3.10 v1(64.57,73.18) ; U13.6 v1(28.94,23.42) ; C21.2 v1(27.45,34.46) ; C73.2 v1(17.29,17.74) ; C81.2 v1(22.97,24.77) ; v1(24.12,39.25) 24.53,39.26 C34.2 ; R76.2 v1(44.06,36.61) ; C76.2 v1(25.84,30.51) ; U9.A1 v1(26.43,64.7) ; C31.2 v1(21.52,40.78) ; C79.2 v1(26.11,16.7) ; C64.2 v1(51.72,28.5) ; C77.2 v1(27.21,30.4) ; C78.2 v1(25.24,19.16) ; J1.A12 v1(64.99,59.54) ; R77.1 v1(46.19,35.74) ; R87.2 v1(23.36,13.91) ; C24.2 v1(28.66,35.14) ; C82.2 v1(52.54,35.76) ; J3.2 v1(54.41,73.28) ; C28.2 v1(19.63,37.06) ; C57.1 v1(38.97,56.79) ; R78.1 v1(51.87,36.27) ; R86.2 v1(17.65,13.3) ; C32.2 v1(30.87,34.87)
  TOP w0.241: R58.2 v1(39.49,65.41) ; R34.2 v1(25.56,59.31) ; C41.2 v1(29.27,52.32) ; C6.1 v1(44.29,55.46) ; v1(44.23,32.21) 44.03,32.4 U11.5 ; R64.1 v1(25.46,62.31) ; C37.2 v1(35.3,39.05) ; C58.1 v1(26.72,67.88) ; R60.2 v1(38.92,62.51) ; U7.4 v1(46.57,44.22) ; R62.2 v1(26.86,56.64) ; C42.2 v1(33.59,50.88) ; C59.1 v1(22.82,62.03) ; R63.2 v1(28.58,56.69) ; C26.2 v1(25.2,52.1) ; C50.1 27.63,67.32 v1(27.59,67.36) R55.2 ; U1.20 49.33,56.05 U1.21 49.33,55.55 U1.11 ; C53.1 36.38,66.38 36.41,66.4 C52.1 v1(36.93,67.96) ; C61.1 v1(23.67,57.7) ; U9.L1 v1(27.23,59.17) ; C15.2 v1(22.06,8.61) ; R88.2 v1(49.98,19.72) ; U12.2 v1(41.79,50.77) ; C18.2 v1(41.38,38.79) ; C40.2 v1(26.32,52.07) ; R16.1 v1(22.23,53.34) ; v1(61.52,52.96) U2.8 U2.3 ; R33.2 v1(25.38,60.45) ; C55.1 v1(24.49,60.3) ; C4.1 v1(43.57,54.89) ; R61.2 v1(33.18,66.34) ; C23.2 v1(37.35,44.91) ; U6.58 v1(22.97,43.51) ; C51.1 v1(35.72,59.13) ; U1.5 48.58,56.05 v1(48.75,55.88) ; C44.2 v1(30.39,52.32) ; R65.2 v1(27.06,55.75) ; C29.2 v1(21.64,38.65) ; R32.2 v1(20.9,62.37) ; R71.1 v1(40.83,48.44) ; C72.2 v1(51.95,31.95) ; C43.2 v1(34.76,50.85) ; C39.2 v1(36.2,48.06) ; R54.2 v1(26.32,56.54) ; C54.1 v1(36.53,62.43) ; C74.2 v1(33,29.51) ; C22.2 v1(37.35,44.04) ; v1(61.59,59.46) 61.56,59.44 U3.8 U3.3 ; C27.2 v1(35.97,51.82) ; R51.2 v1(20.85,64.1) ; C60.1 v1(22.39,64.08) ; C35.2 v1(36,38.46) ; R72.1 v1(39.28,37.26)
  L2_GND w0.102: J4.4 68.14,13.69 ; J4.4 66.81,12.36 ; J4.4 69.47,12.36 ; J4.4 68.14,11.02 ; J1.10 64.04,61.31 ; J1.10 64.04,59.16 ; J1.10 63.27,60.24 ; 63.27,51.99 J1.8 ; J1.8 65.97,51.99 ; J1.8 64.62,51.21 ; 64.04,51.21 J1.9 ; J1.9 64.04,53.36 ; J1.9 63.27,52.29 ; 60.84,8.74 J2.1 ; J2.1 62.67,8.74 ; J2.1 61.76,7.82 ; J2.1 61.76,9.65 ; 59.51,13.26 J4.2 ; J4.2 60.84,14.59 ; J4.2 60.84,11.93 ; J4.2 62.17,13.26 ; 68.14,20.93 J4.5 ; J4.5 66.81,22.26 ; J4.5 69.47,22.26 ; J1.6 64.57,57.26 ; J1.6 64.04,56.61 ; J1.6 64.04,57.91 ; J1.6 63.52,57.26 ; J1.1 67.62,52.79 ; J1.1 67.06,53.34 ; J1.1 66.51,52.79 ; J1.1 67.06,52.23 ; J1.7 64.62,61.31 ; J1.7 63.27,60.54 ; J1.7 65.97,60.54 ; 67.06,59.18 J1.2 ; J1.2 66.51,59.74 ; J1.2 67.06,60.29 ; J1.2 67.62,59.74 ; 59.51,18.46 J4.3 ; J4.3 60.84,17.12 ; J4.3 60.84,19.79 ; J4.3 62.17,18.46 ; 67.92,51.76 J1.3 ; J1.3 69.29,52.44 ; J1.3 69.29,51.08 ; 69.29,60.08 J1.4 ; J1.4 69.29,61.44 ; J1.4 67.92,60.76 ; J1.5 64.57,55.26 ; J1.5 64.04,55.91 ; J1.5 64.04,54.61 ; J1.5 63.52,55.26
  L2_GND w1.372: 49.72,44.54 MH1.1 ; MH1.1 49.72,52.52 ; MH1.1 53.71,48.53 ; MH1.1 45.73,48.53
  L5_GND w0.102: 60.84,8.74 J2.1 ; J2.1 61.76,9.65 ; J2.1 62.67,8.74 ; J2.1 61.76,7.82 ; 68.14,20.93 J4.5 ; J4.5 66.81,22.26 ; J4.5 69.47,22.26 ; J4.2 62.17,13.26 ; J4.2 60.84,14.59 ; J4.2 59.51,13.26 ; J4.2 60.84,11.93 ; J1.4 69.29,61.44 ; J1.4 69.29,60.08 ; J1.4 67.92,60.76 ; J1.1 67.62,52.79 ; J1.1 67.06,53.34 ; J1.1 66.51,52.79 ; J1.1 67.06,52.23 ; J1.3 69.29,52.44 ; J1.3 67.92,51.76 ; J1.3 69.29,51.08 ; J1.2 67.62,59.74 ; J1.2 66.51,59.74 ; J1.2 67.06,59.18 ; J1.2 67.06,60.29 ; 63.52,57.26 J1.6 ; J1.6 64.57,57.26 ; J1.6 64.04,56.61 ; J1.6 64.04,57.91 ; 64.62,51.21 J1.8 ; J1.8 65.97,51.99 ; J1.8 63.27,51.99 ; J1.5 64.04,55.91 ; J1.5 63.52,55.26 ; J1.5 64.57,55.26 ; J1.5 64.04,54.61 ; 63.27,60.54 J1.7 ; J1.7 64.62,61.31 ; J1.7 65.97,60.54 ; J1.10 64.04,61.31 ; J1.10 63.27,60.24 ; J1.10 64.04,59.16 ; J4.3 60.84,19.79 ; J4.3 60.84,17.12 ; J4.3 59.51,18.46 ; J4.3 62.17,18.46 ; 64.04,51.21 J1.9 ; J1.9 64.04,53.36 ; J1.9 63.27,52.29 ; 66.81,12.36 J4.4 ; J4.4 68.14,11.02 ; J4.4 68.14,13.69 ; J4.4 69.47,12.36
  L5_GND w1.372: MH1.1 53.71,48.53 ; MH1.1 45.73,48.53 ; MH1.1 49.72,44.54 ; MH1.1 49.72,52.52
  BOTTOM w0.191: C62.1 v1(58.34,65.21) ; U10.4 v1(64.85,70.48) ; v1(28.87,22.49) 28.3,23.06 28.3,23.93 v1(27.44,24.79)
  BOTTOM w0.241: v1(68.21,58.87) 68.86,59.52 C1.1 ; C5.1 67.87,55.27 68.11,55.51 68.85,55.51 v1(69.14,55.8) ; R1.1 v1(69.38,57.07) ; CN1.P4 v1(25.16,2.85) ; U5.8 U5.3 v1(59.7,56.31) ; CN1.S7 v1(15,2.78) ; C2.1 64.44,56.87 J1.6 ; CN1.S4 v1(11.19,2.78) ; CN1.S1 v1(7.38,2.81) ; U4.3 U4.8 v1(57.54,56.25) ; CN1.P12 v1(35.32,2.87) ; R2.1 67.62,57.53 68.18,56.97 v1(68.18,56.93) ; CN1.P6 v1(27.7,2.85) ; C3.1 68.61,53.94 v1(68.3,54.25) ; CN1.P10 v1(32.78,2.89) ; CN1.P5 v1(26.43,2.87)
  vias: v1(20.99,17.48) v1(20.99,16.84) v1(20.99,16.21) v1(21.62,17.48) v1(21.62,16.84) v1(21.62,16.21) v1(23.63,73.81) v1(24.26,73.81) v1(24.9,73.81) v1(25.53,73.81) v1(26.17,73.81) v1(26.8,73.81) v1(27.44,73.81) v1(27.94,45.38) v1(27.94,44.74) v1(27.94,44.11) v1(27.94,43.47) v1(27.94,42.84) v1(28.58,45.38) v1(28.58,44.74) v1(28.58,44.11) v1(28.58,43.47) v1(28.58,42.84) v1(28.81,56.03) v1(29.21,45.38) v1(29.21,44.74) v1(29.21,44.11) v1(29.21,43.47) v1(29.21,42.84) v1(29.75,57.86) v1(29.85,45.38) v1(29.85,44.74) v1(29.85,44.11) v1(29.85,43.47) v1(29.85,42.84) v1(29.98,62.46) v1(29.98,61.95) v1(30.11,56.06) v1(30.49,62.46) v1(30.49,61.95) v1(30.48,45.38) v1(30.48,44.74) v1(30.48,44.11) v1(30.48,43.47) v1(30.48,42.84) v1(30.95,57.84) v1(30.98,62.46) v1(30.98,61.95) v1(31.12,18.59) v1(31.12,17.96) v1(31.12,17.32) v1(31.12,16.69) v1(31.12,16.05) v1(31.53,52.81) v1(31.76,18.59) v1(31.76,17.96) v1(31.76,17.32) v1(31.76,16.69) v1(31.76,16.05) v1(32.16,57.84) v1(32.39,18.59) v1(32.39,17.96) v1(32.39,17.32) v1(32.39,16.69) v1(32.39,16.05) v1(32.82,52.98) v1(37.9,72.87) v1(38.54,72.87) v1(39.17,72.87) v1(39.81,72.87) v1(40.44,72.87) v1(41.08,72.87) v1(41.71,72.87) v1(43.49,66.07) v1(43.49,65.43) v1(43.49,64.8) v1(43.49,64.16) v1(44.23,34.11) v1(44.23,33.48) v1(44.23,32.84) v1(44.23,31.57) v1(44.23,30.94) v1(44.23,30.3) v1(44.23,29.67) v1(44.86,34.11) v1(44.86,33.48) v1(44.86,32.84) v1(44.86,32.21) v1(44.86,31.57) v1(44.86,30.94) v1(44.86,30.3) v1(44.86,29.67) v1(45.5,34.11) v1(45.5,33.48) v1(45.5,32.84) v1(45.5,32.21) v1(45.5,31.57) v1(45.5,30.94) v1(45.5,30.3) v1(45.5,29.67) v1(46.13,34.11) v1(46.13,33.48) v1(46.13,32.84) v1(46.13,32.21) v1(46.13,31.57) v1(46.13,30.94) v1(46.13,30.3) v1(46.13,29.67) v1(46.77,34.11) v1(46.77,33.48) v1(46.77,32.84) v1(46.77,32.21) v1(46.77,31.57) v1(46.77,30.94) v1(46.77,30.3) v1(46.77,29.67) v1(47.48,24.49) v1(47.48,23.85) v1(48.12,24.49) v1(48.12,23.85) v1(48.75,56.52) v1(48.75,55.24) v1(48.75,24.49) v1(48.75,23.85) v1(49.39,56.52) v1(49.39,55.88) v1(49.39,55.24) v1(59.06,5.38) v1(59.06,4.75) v1(59.06,4.11) v1(59.06,3.48) v1(59.06,2.84) v1(59.7,5.38) v1(59.7,4.75) v1(59.7,4.11) v1(59.7,3.48) v1(59.7,2.84) v1(60.33,5.38) v1(60.33,4.75) v1(60.33,4.11) v1(60.33,3.48) v1(60.33,2.84) v1(61.8,57.85) v1(62.16,54.43) v1(62.57,55.58) v1(68.19,53.58) v1(68.3,58.26)
SV5: length 3.3
  TOP w0.191: v1(28.97,2.87) 28.61,3.23 R5.2
  BOTTOM w0.241: CN1.P7 v1(28.97,2.87)
SV12: length 3.2
  TOP w0.191: R10.2 36.2,3.29 v1(36.59,2.9)
  BOTTOM w0.241: CN1.P13 v1(36.59,2.9)
SV33: length 3.2
  TOP w0.191: v1(23.89,2.8) 23.89,3.15 24.09,3.35 R7.2
  BOTTOM w0.241: CN1.P3 v1(23.89,2.8)
VDD_1P1V: length 32.7
  TOP w0.191: v1(30.79,37.69) 30.61,37.88 U6.12 ; C39.1 33.89,48.06 v1(33.41,47.58) ; C30.1 23.48,41.11 v1(23.48,41.51) 23.87,41.51 U6.63 ; C38.1 21.24,39.45 v1(21.49,39.19) ; C35.1 33.74,38.46 v1(32.95,39.24) ; v1(35.56,49.19) C43.1 34.11,49.19 34.09,49.21 C42.1 33.13,48.63 33.09,48.63 v1(32.77,48.31) U6.33 ; 30.87,37.62 31.72,36.77 C36.1 ; v1(21.49,39.19) C28.1 ; v1(21.49,39.19) 22,39.69 C29.1 ; FB3.2 v1(36.23,49.38) ; v1(33.28,39.85) 33.56,39.57 C37.1 ; v1(29.27,49.83) 29.01,49.58 U6.41 ; C34.1 25.32,40.3 v1(25.71,39.91) ; v1(26.4,49.73) 26.61,49.52 U6.47 ; v1(23.49,42.31) 22.98,41.99 22.82,41.82 C31.1 ; U6.55 v1(26.22,44.71)
  TOP w0.241: v1(29.27,49.83) C41.1 C44.1 ; v1(23.49,42.31) 23.82,42.31 U6.61 ; C40.1 26.32,49.81 v1(26.4,49.73) ; U6.49 v1(25.01,47.59) 24.93,47.68 C33.1 ; U6.19 v1(32.09,41.91) ; v1(30.79,37.69) 30.87,37.62 C32.1 ; U6.32 v1(33.41,47.58) ; U6.1 v1(25.71,39.91)
VDD_3P3V: length 15.7
  TOP w0.191: v1(34.93,44.48) 35.36,44.04 C22.1 ; v1(34.93,44.48) 34.36,43.91 U6.24 ; v1(34.93,44.48) 35.36,44.91 C23.1 ; U6.7 28.61,38.28 v1(28.41,38.07) ; v1(28.41,38.07) 28.66,37.82 C24.1 ; v1(28.41,38.07) 28.01,37.68 28.01,37.36 27.47,36.83 C21.1 ; R83.2 v1(17.65,15.84) ; R81.1 v1(23.52,20.56) ; R85.2 v1(24.82,21.29)
  TOP w0.241: R14.2 v1(38.41,45.97) ; FB1.2 v1(39.23,45.8) ; C25.1 23.78,47.49 23.66,47.36 v1(23.66,46.91) 23.66,46.56 23.91,46.31 U6.51 ; R15.2 v1(37.74,47.74)
VDDA_3P3V: length 9.8
  TOP w0.191: U6.40 v1(29.41,47.03) ; C26.1 25.2,50.1 v1(25.75,49.56) 26.21,49.1 U6.48
  TOP w0.241: U6.62 v1(26.24,41.91) ; FB2.2 v1(23.86,51.1) ; C27.1 33.46,51.79 32.9,51.23 32.9,50.75 v1(31.81,49.66) U6.34
VIN_3V3: length 9
  TOP w0.191: FB8.2 C55.2 25.15,61.21 25.26,61.1 v1(26.84,61.1) ; U9.B1 v1(26.86,64.2)
  TOP w0.241: U9.H1 27.66,61.11 27.29,61.11 27.29,61.1 v1(26.84,61.1)
  L4_PWR w0.191: v1(26.84,61.1) 26.52,61.42 26.52,63.86 v1(26.86,64.2)
VSSOSC: length 11.3
  TOP w0.191: U6.53 23.48,45.51 21.98,47 X1.2 21.78,47 21.06,47.73 20.76,47.73 19.68,48.8 X1.4 19.48,48.8 18.66,47.98 17.24,47.98 C20.2 C19.2
3212OEN: length 2.5
  TOP w0.191: U1.2 47.07,57.55 R4.2 R3.2
53318_EN: length 6
  TOP w0.191: v1(42.32,36.86) R67.1 R72.2 ; U11.2 v1(42.25,33.9)
  BOTTOM w0.191: v1(42.32,36.86) 42.32,34.42 42.25,34.35 v1(42.25,33.9)
53318_MODE: length 5.4
  TOP w0.191: U11.20 48.65,33.4 49.28,34.04 49.28,35.27 R78.2 R74.1
65982_5V: length 0.4
  TOP w0.241: U9.H10 v1(31.82,61.2)
  vias: v1(33.13,64.49) v1(33.13,63.96) v1(33.64,64.49) v1(33.64,63.96)
65982_VBUS:
  vias: v1(33.31,72.05) v1(33.31,71.5) v1(33.41,72.59) v1(33.66,60.86) v1(33.66,60.35) v1(34.04,72.59) v1(34.12,60.86) v1(34.12,60.35) v1(34.58,60.86) v1(34.58,60.35) v1(34.68,72.59)
87501_S1: length 2.2
  TOP w0.241: U8.B1 v1(33.77,68.56) ; v1(32.34,65.15) 32.23,65.04 U9.A10 ; U8.E1 v1(35.72,68.57) ; U8.D1 v1(35.07,68.57) ; U8.A1 v1(33.12,68.56)
  vias: v1(36.45,69.14) v1(36.43,68.69) v1(36.92,69.15) v1(36.91,68.7)
AUX_N: length 2.4
  TOP w0.102: R34.1 26.5,59.82 27.16,60.48 28.01,60.48 U9.J2
AUX_P: length 1.4
  TOP w0.102: R33.1 26.78,60.45 27.03,60.7 U9.J1
BOARD_1P1V: length 0.8
  TOP w0.191: FB3.1 v1(37.8,49.35)
  vias: v1(30.67,30.81) v1(30.67,30.18) v1(30.67,29.54) v1(30.89,27.71) v1(31.3,30.81) v1(31.3,30.18) v1(31.3,29.54) v1(31.53,27.71)
BOARD_3P3V: length 11.6
  TOP w0.191: D3.2 46.53,21.23 v1(46.54,21.23) ; R8.2 41.58,45.91 v1(41.21,45.54) ; v1(38.01,39.75) 38.01,39.75 R6.2
  TOP w0.241: C18.1 v1(38.69,38.79) ; v1(46.03,56.01) 46.09,56.01 C6.2 ; C4.2 v1(46.03,54.89) ; R17.1 v1(24.16,28.07) ; R6.2 38.6,40.52 38.71,40.41 U7.8 v1(41.79,40.41) ; FB1.1 v1(40.8,45.8) ; FB2.1 v1(23.86,52.91) ; FB8.1 v1(23.1,58.93)
  vias: v1(21.37,3.2) v1(21.37,2.57) v1(22,3.2) v1(22,2.57) v1(22.64,3.2) v1(22.64,2.57) v1(27.24,27.08) v1(27.92,28.09) v1(27.92,27.61)
BOARD_5V: length 17
  TOP w0.191: 38.57,23.92 36.51,25.98 36.51,34.92 37.47,35.89 R69.1
  TOP w0.241: C69.2 v1(38.25,34.02) ; 38.57,23.92 L1.2
  vias: v1(18.25,18.64) v1(18.25,18.19) v1(18.25,17.73) v1(18.83,18.64) v1(18.83,18.19) v1(18.83,17.73) v1(29.09,73.61) v1(29.09,72.97) v1(29.09,72.34) v1(29.73,73.61) v1(29.73,72.97) v1(29.73,72.34) v1(38.08,64.72) v1(38.08,64.08) v1(38.59,64.72) v1(38.59,64.08) v1(40.65,22.96) v1(40.65,22.33) v1(41.28,22.96) v1(41.28,22.33) v1(41.92,22.96) v1(41.92,22.33) v1(42.55,22.96) v1(42.55,22.33) v1(43.19,22.96) v1(43.19,22.33)
BOARD_12V: length 10.3
  TOP w0.102: U9.B10 v1(31.76,63.73)
  TOP w0.191: R67.2 v1(43.35,38.57)
  TOP w0.241: R66.2 v1(43.38,49.47)
  TOP w0.864: 60.84,20.52 J4.1 ; J4.1 59.51,21.86 ; J4.1 62.17,21.86
  L4_PWR w0.864: 60.84,20.52 J4.1 ; J4.1 62.17,21.86 ; J4.1 59.51,21.86
  vias: v1(31.12,73.61) v1(31.12,72.97) v1(31.12,72.34) v1(31.76,73.61) v1(31.76,72.97) v1(31.76,72.34) v1(44.28,68.91) v1(44.28,68.28) v1(44.28,67.64) v1(44.92,68.91) v1(44.92,68.28) v1(44.92,67.64) v1(48.93,31.57) v1(48.93,30.94) v1(48.93,30.3) v1(48.93,29.67) v1(48.93,29.03) v1(54.97,18.31) v1(54.97,17.68) v1(54.97,17.04) v1(54.97,16.41) v1(54.97,15.77) v1(55.61,18.31) v1(55.61,17.68) v1(55.61,17.04) v1(55.61,16.41) v1(55.61,15.77) v1(56.24,18.31) v1(56.24,17.68) v1(56.24,17.04) v1(56.24,16.41) v1(56.24,15.77) v1(56.88,18.31) v1(56.88,17.68) v1(56.88,17.04) v1(56.88,16.41) v1(56.88,15.77) v1(57.51,18.31) v1(57.51,17.68) v1(57.51,17.04) v1(57.51,16.41) v1(57.51,15.77)
C_CC1: length 46.4
  TOP w0.102: R28.1 34.04,58.06 33.2,58.06 31.73,59.53 U9.L9
  TOP w0.191: J1.A5 65.71,55.51 v1(65.84,55.64) ; R28.1 36.75,56.46 C57.2
  TOP w0.241: C57.2 v1(37.13,56.15)
  L4_PWR w0.191: v1(57.54,55.15) 57.54,52.43 58.07,51.89 61.98,51.89 62.95,52.86 62.95,53.26 63.51,53.82 65.29,53.82 65.77,54.31 66.17,54.31 66.56,54.69 66.56,55.37 66.29,55.64 v1(65.84,55.64)
  BOTTOM w0.191: U4.1 54.66,55.25 54.54,55.37 52.13,55.37 50.58,53.82 37.75,53.82 37.13,54.44 v1(37.13,56.15)
  BOTTOM w0.241: v1(57.54,55.15) 57.47,55.24 57.34,55.24 57.33,55.25 U4.10 U4.1
C_CC2: length 48.3
  TOP w0.102: U9.L10 32.23,59.63 33.39,58.47 34.76,58.47 R29.1
  TOP w0.191: R29.1 36.57,57.58 C56.2 37.13,58.71 37.37,58.95 39.15,58.95 39.58,58.52 v1(39.58,55.02)
  TOP w0.241: J1.B5 v1(67.48,57.01)
  L4_PWR w0.191: v1(57.54,55.7) 57.86,55.7 58.07,55.49 58.07,52.64 58.31,52.4 61.73,52.4 62.52,53.19 62.52,53.62 63.23,54.33 64.45,54.33 65.01,54.89 65.01,55.83 65.49,56.31 66.78,56.31 v1(67.48,57.01)
  BOTTOM w0.191: v1(39.58,55.02) 41.97,55.02 42.68,54.31 50.1,54.31 51.67,55.88 55.28,55.88 55.45,55.71 56.07,55.71 U4.2
  BOTTOM w0.241: v1(57.54,55.7) 57.5,55.75 U4.9 U4.2
C_USB_BN: length 43.4
  TOP w0.102: U9.L7 30.73,59.51
  TOP w0.14: 30.73,59.51 30.72,59.49 30.72,59.2 31.42,58.5 31.42,58.42 v1(31.28,58.28) ; v1(67.79,55.99) 67.66,56.13 67.62,56.13 67.62,56.13 66.82,56.13 J1.B7
  BOTTOM w0.14: v1(31.28,58.28) 31.43,58.13 31.43,57.4 32.06,56.77 33.08,56.77 34.37,58.06 43.49,58.06 44.97,59.54 56.85,59.54 59.45,56.94 60.21,56.94 U5.4 U5.7 61.22,56.94 62.3,56.94 63.1,56.13 66.7,56.13 66.9,55.93 67.12,55.93 67.32,56.13 67.65,56.13 v1(67.79,55.99)
C_USB_BP: length 43.4
  TOP w0.102: U9.K7 30.97,59.97 30.97,59.39
  TOP w0.14: 30.97,59.39 30.97,59.31 31.67,58.61 31.67,58.42 v1(31.81,58.28) ; J1.B6 66.82,56.39 67.62,56.39 67.62,56.39 67.66,56.39 v1(67.79,56.53)
  BOTTOM w0.14: v1(31.81,58.28) 31.68,58.15 31.68,57.51 32.17,57.02 32.97,57.02 34.27,58.32 43.39,58.32 44.86,59.79 56.95,59.79 59.56,57.19 60.21,57.19 U5.5 U5.6 61.22,57.19 62.4,57.19 63.2,56.39 67.65,56.39 v1(67.79,56.53)
C_USB_TN: length 43.3
  TOP w0.14: J1.A7 64.87,56.39 63.79,56.39 63.49,56.69 61.48,56.69 61.04,56.26 61.04,55.75 61.36,55.43 61.93,55.43 v1(62.07,55.3) ; U9.L6 30.22,59.69 30.22,59 30.23,58.99 30.23,58.42 v1(30.09,58.28)
  BOTTOM w0.14: v1(62.07,55.3) 61.93,55.43 61.22,55.43 U5.10 U5.1 60.21,55.43 59.13,55.43 56.76,53.06 34.48,53.06 30.23,57.3 30.23,58.14 v1(30.09,58.28)
C_USB_TP: length 43.3
  TOP w0.102: U9.K6 30.49,59.95 30.49,59.6
  TOP w0.14: 30.49,59.6 30.48,59.59 30.48,59.1 30.49,59.09 30.49,58.42 v1(30.63,58.28) ; v1(62.07,55.83) 61.93,55.69 61.47,55.69 61.3,55.86 61.3,56.16 61.58,56.44 62.69,56.44 62.77,56.36 62.77,56.1 62.85,56.02 62.96,56.02 63.04,56.1 63.04,56.36 63.12,56.44 63.38,56.44 63.69,56.13 64.87,56.13 J1.A6
  BOTTOM w0.14: v1(30.63,58.28) 30.49,58.14 30.49,57.41 34.58,53.31 56.65,53.31 59.02,55.69 60.21,55.69 U5.2 U5.9 61.22,55.69 61.93,55.69 v1(62.07,55.83)
CABLE_PLUG: length 7.2
  TOP w0.102: R13.2 21.09,53.73 21.98,54.61 25.08,54.61 25.52,55.05 R90.1
CAP_SATARXM: length 2.2
  TOP w0.14: v1(12.83,2.51) 12.83,2.52 12.83,2.9 12.54,3.19 C12.1
  BOTTOM w0.14: v1(12.83,2.51) 12.83,1.61 CN1.S5
CAP_SATARXP: length 2.2
  TOP w0.14: C13.1 13.66,3.19 13.37,2.9 13.37,2.52 v1(13.36,2.51)
  BOTTOM w0.14: v1(13.36,2.51) 13.36,1.61 CN1.S6
CAP_SATATXM: length 2.2
  TOP w0.14: C11.1 8.73,3.19 9.02,2.9 9.02,2.52 v1(9.02,2.51)
  BOTTOM w0.14: CN1.S2 9.02,1.61 v1(9.02,2.51)
CAP_SATATXP: length 2.2
  TOP w0.14: v1(9.55,2.51) 9.58,2.54 9.58,2.92 9.85,3.19 C14.1
  BOTTOM w0.14: v1(9.55,2.51) 9.55,1.61 CN1.S3
CRX1N: length 19.9
  TOP w0.14: J1.B10 66.82,54.39 67.65,54.39 v1(67.79,54.53) ; v1(61.82,53.98) 61.69,53.84 61.65,53.84 61.65,53.84 60.97,53.84 U2.10 U2.1 60.04,53.96 59.91,53.84 57.05,53.84 55.45,55.43 50.4,55.43 U1.15
  BOTTOM w0.14: v1(67.79,54.53) 67.65,54.39 64.35,54.39 63.8,53.84 61.96,53.84 v1(61.82,53.98)
CRX1P: length 19.9
  TOP w0.14: v1(67.79,53.99) 67.65,54.13 66.82,54.13 J1.B11 ; U1.14 50.4,55.17 55.35,55.17 56.94,53.58 59.95,53.58 U2.2 U2.9 60.97,53.58 61.68,53.58 v1(61.82,53.44)
  BOTTOM w0.14: v1(67.79,53.99) 67.65,54.13 64.45,54.13 63.9,53.58 61.96,53.58 v1(61.82,53.44)
CRX2N: length 16.9
  TOP w0.14: J1.A10 64.87,58.14 63.58,58.14 61.66,60.06 60.97,60.06 U3.9 U3.2 59.95,60.06 53.84,60.06 50.96,57.17 50.4,57.17 U1.18
CRX2P: length 16.9
  TOP w0.14: U1.19 50.4,57.43 50.85,57.43 53.74,60.31 59.95,60.31 U3.1 U3.10 60.97,60.31 61.76,60.31 63.68,58.39 64.87,58.39 J1.A11
CSBU1: length 36.1
  TOP w0.191: v1(38.92,55.64) 35.91,55.64 34.53,57.02 R31.1
  TOP w0.241: J1.A8 65.73,57.01 v1(65.83,56.91)
  L4_PWR w0.191: v1(57.54,56.8) 62.51,56.8 63.13,56.18 64.22,56.18 64.94,56.91 v1(65.83,56.91)
  BOTTOM w0.191: v1(38.92,55.64) 43.66,55.64 45.79,57.76 54.29,57.76 55.3,56.75 U4.4
  BOTTOM w0.241: v1(57.54,56.8) 57.5,56.75 U4.7 U4.4 ; R2.2 66.47,57.44 65.93,56.91 v1(65.83,56.91)
CSBU1_TPS65982: length 4.1
  TOP w0.102: R31.2 33.38,57.59 31.46,59.51 31.46,59.98 U9.K8
CSBU2: length 44
  TOP w0.191: v1(37.93,55.12) 35.75,55.12 34.48,56.39 R30.1 ; v1(68.5,56) 68.01,55.51 J1.B8
  L4_PWR w0.191: v1(57.54,57.35) 57.54,58.06 59.57,60.1 62.06,60.1 63.86,58.29 66.28,58.29 67.03,57.54 68.52,57.54 68.77,57.3 68.77,56.71 68.5,56.45 v1(68.5,56)
  BOTTOM w0.191: v1(37.93,55.12) 37.93,55.57 38.67,56.31 43.63,56.31 45.56,58.24 54.59,58.24 55.58,57.25 U4.5
  BOTTOM w0.241: U4.5 U4.6 56.94,57.26 57.47,57.26 v1(57.54,57.35) ; v1(68.5,56) 68.76,56.26 R1.2
CSBU2_TPS65982: length 4.4
  TOP w0.102: U9.L8 31.23,59.45 32.67,58.01 32.67,56.72 33,56.39 R30.2
CTX1N: length 7.5
  TOP w0.14: C9.2 59.29,52.34 59.95,52.34 U2.4 U2.7 60.97,52.34 62.28,52.34 62.67,52.73 62.67,53.75 63.31,54.39 64.87,54.39 J1.A3
CTX1N_C: length 9.2
  TOP w0.14: C9.1 58.39,52.34 56.81,52.34 54.73,54.43 50.4,54.43 U1.13
CTX1P: length 7.5
  TOP w0.14: C10.2 59.27,52.08 59.95,52.08 U2.5 U2.6 60.97,52.08 62.38,52.08 62.92,52.62 62.92,53.64 63.42,54.13 64.87,54.13 J1.A2
CTX1P_C: length 9.2
  TOP w0.14: U1.12 50.4,54.17 54.62,54.17 56.71,52.09 58.39,52.09 C10.1
CTX2N: length 10.4
  TOP w0.14: v1(61.82,58.42) 61.69,58.55 61.65,58.55 61.65,58.56 60.97,58.56 U3.6 U3.5 59.95,58.56 59.28,58.56 C8.2 ; v1(67.79,57.99) 67.66,58.13 67.62,58.13 67.62,58.13 66.82,58.13 J1.B3
  BOTTOM w0.14: v1(67.79,57.99) 67.65,58.13 66.71,58.13 66.46,58.38 65.43,58.38 65.26,58.56 61.96,58.56 v1(61.82,58.42)
CTX2N_C: length 9.4
  TOP w0.14: C8.1 58.39,58.56 56.44,58.56 54.05,56.17 50.4,56.17 U1.16
CTX2P: length 10.4
  TOP w0.14: v1(67.79,58.53) 67.65,58.39 66.82,58.39 J1.B2 ; v1(61.82,58.95) 61.69,58.82 61.65,58.82 61.65,58.81 60.97,58.81 U3.7 U3.4 59.95,58.81 59.28,58.81 C7.2
  BOTTOM w0.14: v1(61.82,58.95) 61.96,58.81 65.36,58.81 65.54,58.64 66.56,58.64 66.81,58.39 67.65,58.39 v1(67.79,58.53)
CTX2P_C: length 9.4
  TOP w0.14: U1.17 50.4,56.43 53.95,56.43 56.34,58.82 58.39,58.82 C7.1
DBG_CTL1: length 9.3
  TOP w0.102: v1(28.76,62.43) 28.96,62.43 U9.E4
  TOP w0.241: R36.2 v1(22.88,65.34)
  BOTTOM w0.191: v1(28.76,62.43) 28.33,62.43 27.69,63.07 27.69,64.34 26.7,65.33 24.85,65.33 24.54,65.02 23.2,65.02 v1(22.88,65.34)
DBG_CTL2: length 7.7
  TOP w0.102: v1(29.22,63.4) 29.41,63.2 U9.D5
  TOP w0.241: R35.2 v1(24.29,65.51)
  BOTTOM w0.191: v1(24.29,65.51) 24.61,65.83 27.17,65.83 28.9,64.1 28.9,63.72 v1(29.22,63.4)
DEBUG1: length 4.3
  TOP w0.102: R90.2 25.71,57.36 25.71,58.27 26.23,58.79 27.38,58.79 27.47,58.87 27.5,58.9 28.23,59.63 U9.L2
DEBUG2: length 4.1
  TOP w0.102: U9.K2 28.48,59.96 28.48,59.41 27.64,58.57 26.6,58.57 26.32,58.29 R54.1
DEBUG3: length 3.2
  TOP w0.102: R62.1 R56.1 27.47,58.06 28.73,59.33 U9.L3
DEBUG4: length 3.7
  TOP w0.102: U9.K3 28.99,59.94 28.99,59.21 27.97,58.19 R57.1 R63.1
FAULT#: length 44.8
  TOP w0.191: v1(21.86,19.52) R81.2 22.74,19.02 22.79,18.97 U14.10 ; v1(22.79,14.86) 22.8,15.77 U14.6
  TOP w0.241: U6.23 v1(34.78,43.51)
  L3_SIG w0.241: v1(22.79,14.86) 22.79,18.72 v1(21.86,19.52)
  BOTTOM w0.191: v1(21.86,19.52) 23.39,19.52 23.79,19.93 28.04,19.93 32.01,23.9 32.01,32.05 32.71,32.75 32.71,37.48 31.55,38.63 31.55,42.21 31.91,42.57 32.52,42.57 33.46,43.51 v1(34.78,43.51)
FB_DCDC: length 3.7
  TOP w0.191: U13.11 28.24,26.59 28.65,27 R82.2 ; C75.1 R80.2
  TOP w0.241: R82.2 C75.1
FREQSEL0: length 3.4
  TOP w0.241: R14.1 36.2,45.97 35.86,46.31 U6.30
FREQSEL1: length 3.4
  TOP w0.241: R15.1 36.2,47.09 35.81,46.71 U6.31
FUSE_12V:
  vias: v1(37.9,3.17) v1(37.9,2.54) v1(38.54,3.17) v1(38.54,2.54) v1(39.17,3.17) v1(39.17,2.54)
G1: length 5.7
  TOP w0.102: R28.2 34.45,58.27 33.28,58.27 31.99,59.56 31.99,59.95 U9.K9
G2: length 4.9
  TOP w0.102: R29.2 35.16,58.67 33.49,58.67 33.1,59.06 33.1,59.72 32.84,59.97 32.47,59.97 U9.K10
GPIO0: length 2.6
  TOP w0.102: U9.B2 28.51,64.48 28.51,64.9 27.59,65.82 R55.1
GPIO0_9261: length 7.3
  TOP w0.191: R21.2 29.43,34.87 29.43,38.17 29.01,38.59 U6.8
GPIO1: length 4.7
  TOP w0.102: R25.2 25.56,64.85 26.17,64.24 26.18,64.24 26.4,64.01 26.4,64.01 26.63,63.78 27.06,63.78 27.21,63.93 28.01,63.93 U9.C2
GPIO1_9261: length 7
  TOP w0.191: U6.9 29.41,38.77 29.83,38.35 29.83,34.13 R23.2
GPIO2: length 12.7
  TOP w0.102: U9.D10 32.23,63.08 v1(31.73,62.58)
  TOP w0.191: R26.2 v1(41.09,59.2)
  BOTTOM w0.191: v1(31.73,62.58) 32.18,62.58 32.19,62.59 32.33,62.59 33.38,61.54 39.36,61.54 41.09,59.81 v1(41.09,59.2)
GPIO3: length 16.2
  TOP w0.102: U9.G11 33.38,61.7 33.52,61.56 36.52,61.56 36.76,61.32 v1(36.76,59.66)
  TOP w0.241: R27.2 v1(39.09,51.47)
  L4_PWR w0.191: v1(36.76,59.66) 36.76,58.98 37.98,57.76 37.98,56.18 37.4,55.6 37.4,53.16 v1(39.09,51.47)
GPIO3_9261: length 6.5
  TOP w0.191: U6.11 30.21,33.91 30.23,33.89 R18.2
GPIO4: length 8.4
  TOP w0.102: v1(31.73,63.14) 32.23,63.65 U9.C10
  TOP w0.241: R58.1 v1(37.78,65.41)
  BOTTOM w0.191: v1(37.78,65.41) 35.79,65.41 33.53,63.14 v1(31.73,63.14)
GPIO4_9261: length 7.8
  TOP w0.191: U6.13 31.01,38.53 32.02,37.52 32.63,37.52 32.95,37.2 32.95,33.92 R19.2
GPIO5: length 14.6
  TOP w0.102: U9.E10 32.52,62.42 32.96,62.42 33.17,62.2 v1(34.02,62.2)
  TOP w0.191: R59.1 v1(44.31,60.1)
  BOTTOM w0.191: v1(34.02,62.2) 34.98,63.17 36.66,63.17 37.78,62.05 40.37,62.05 42.32,60.1 v1(44.31,60.1)
GPIO5_9261: length 7.8
  TOP w0.191: R20.2 33.69,37.11 32.8,38 32.04,38 31.41,38.63 U6.14
GPIO6: length 5.9
  TOP w0.102: R60.1 37.17,62 36.2,62 36,61.8 33.79,61.8 33.66,61.93 32.46,61.93 U9.G10
GPIO6_9261: length 8.2
  TOP w0.191: U6.15 31.81,38.77 32.2,38.38 33.08,38.38 34.83,36.63 R22.2
